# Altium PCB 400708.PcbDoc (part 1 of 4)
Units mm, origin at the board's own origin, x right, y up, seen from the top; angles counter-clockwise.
Board outline 117 x 63.5 mm, 4 copper layers (Top Layer, Mid-Layer 1, Mid-Layer 2, Bottom Layer), stack 1.556 mm thick; 226 components, 168 nets, 912 pads, 2002 vias.
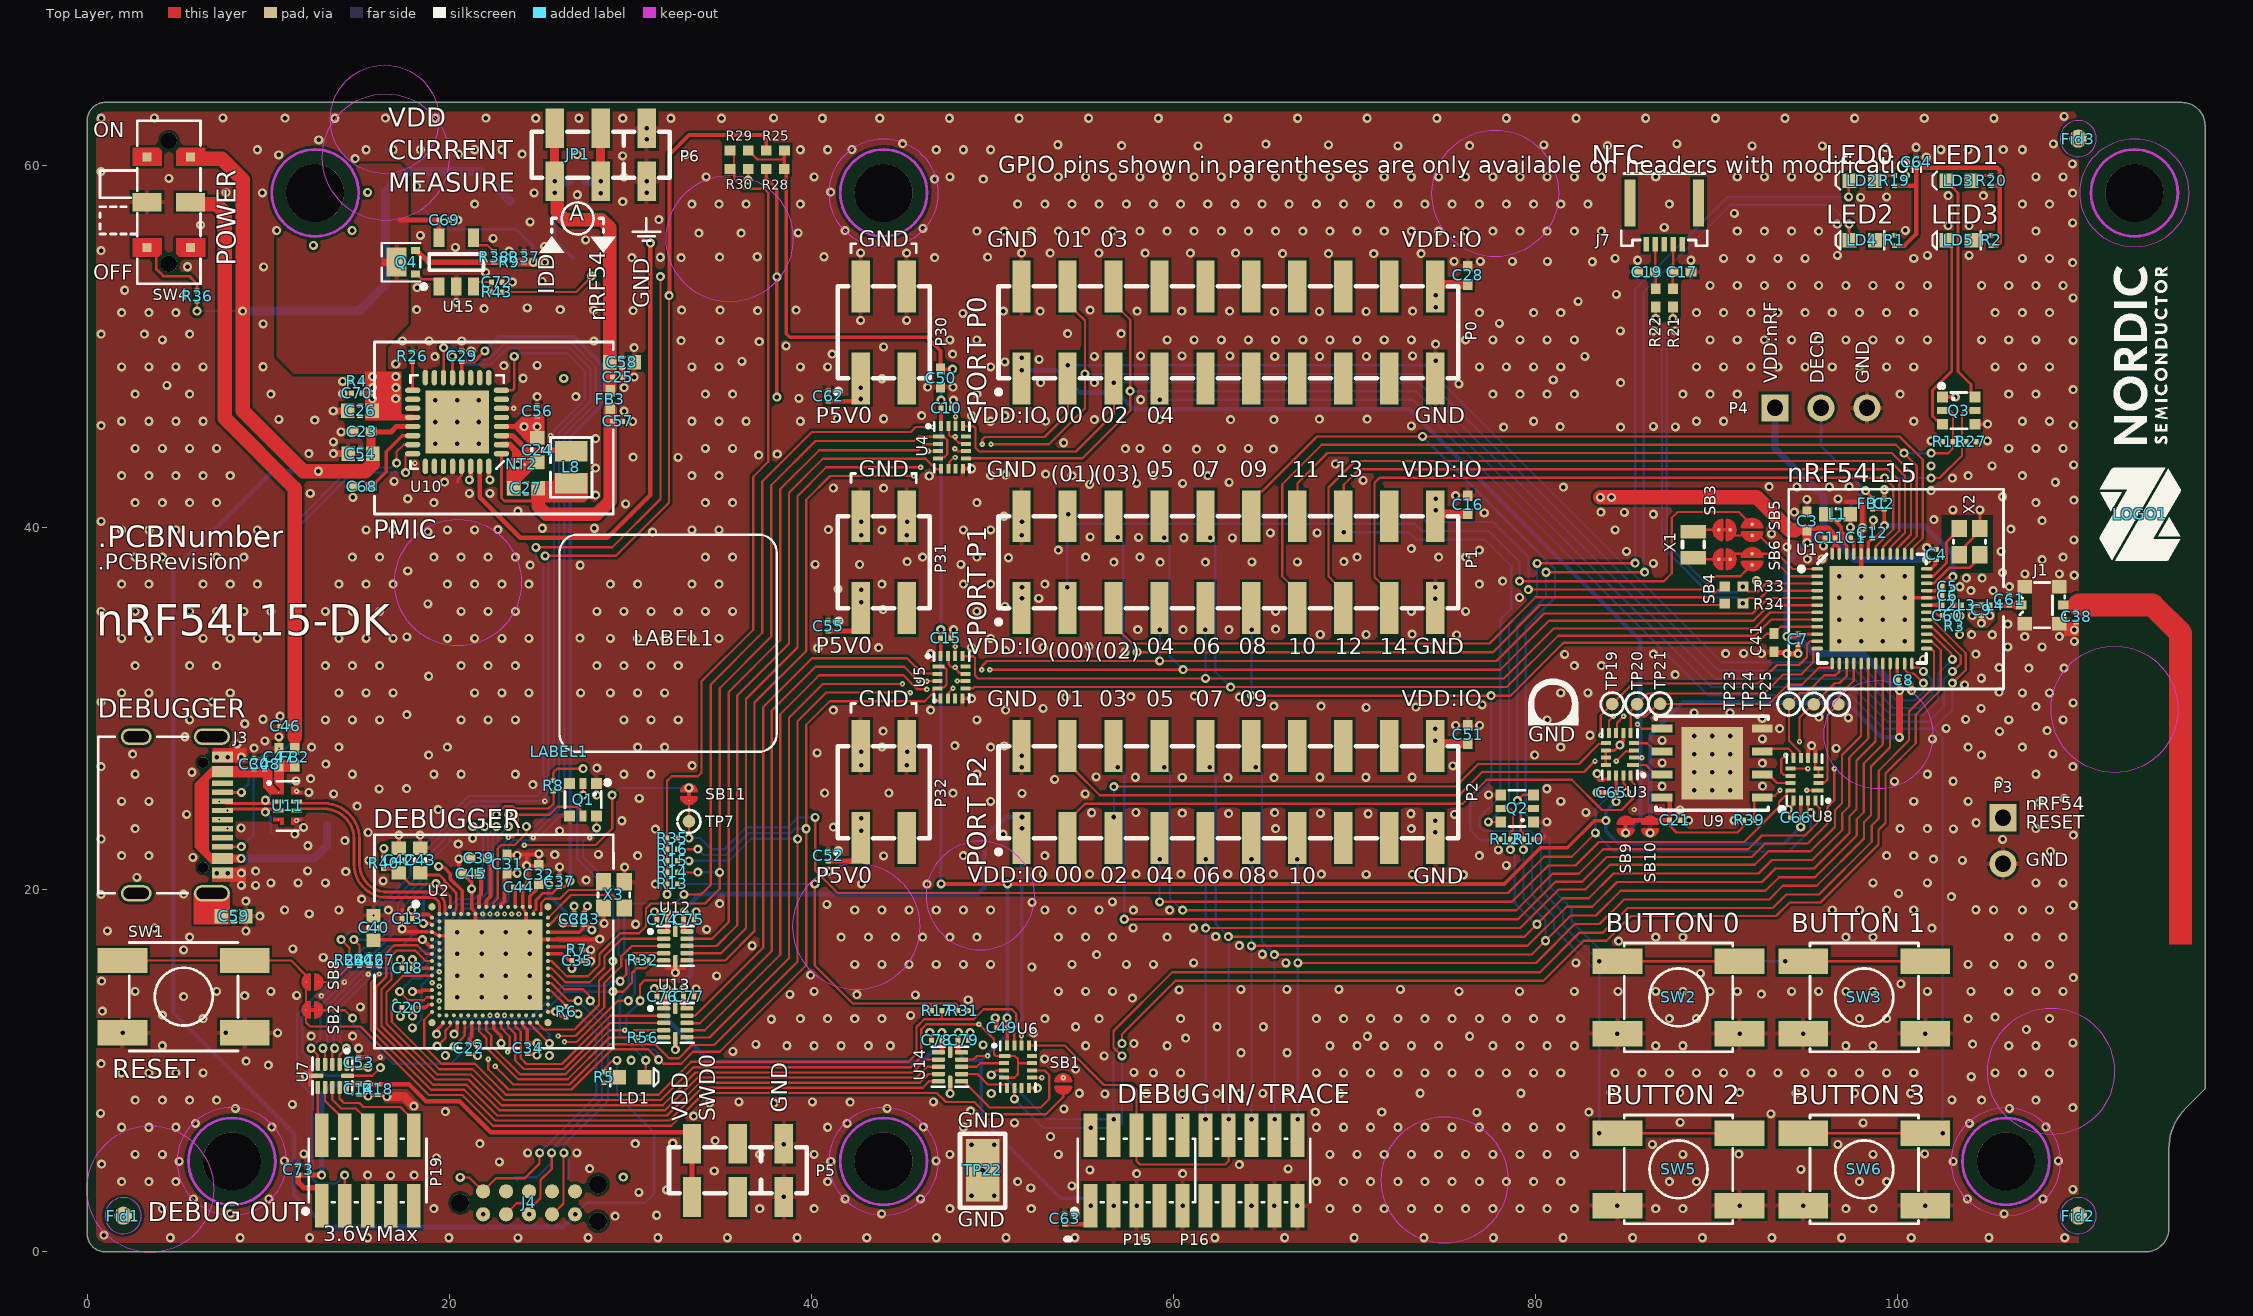
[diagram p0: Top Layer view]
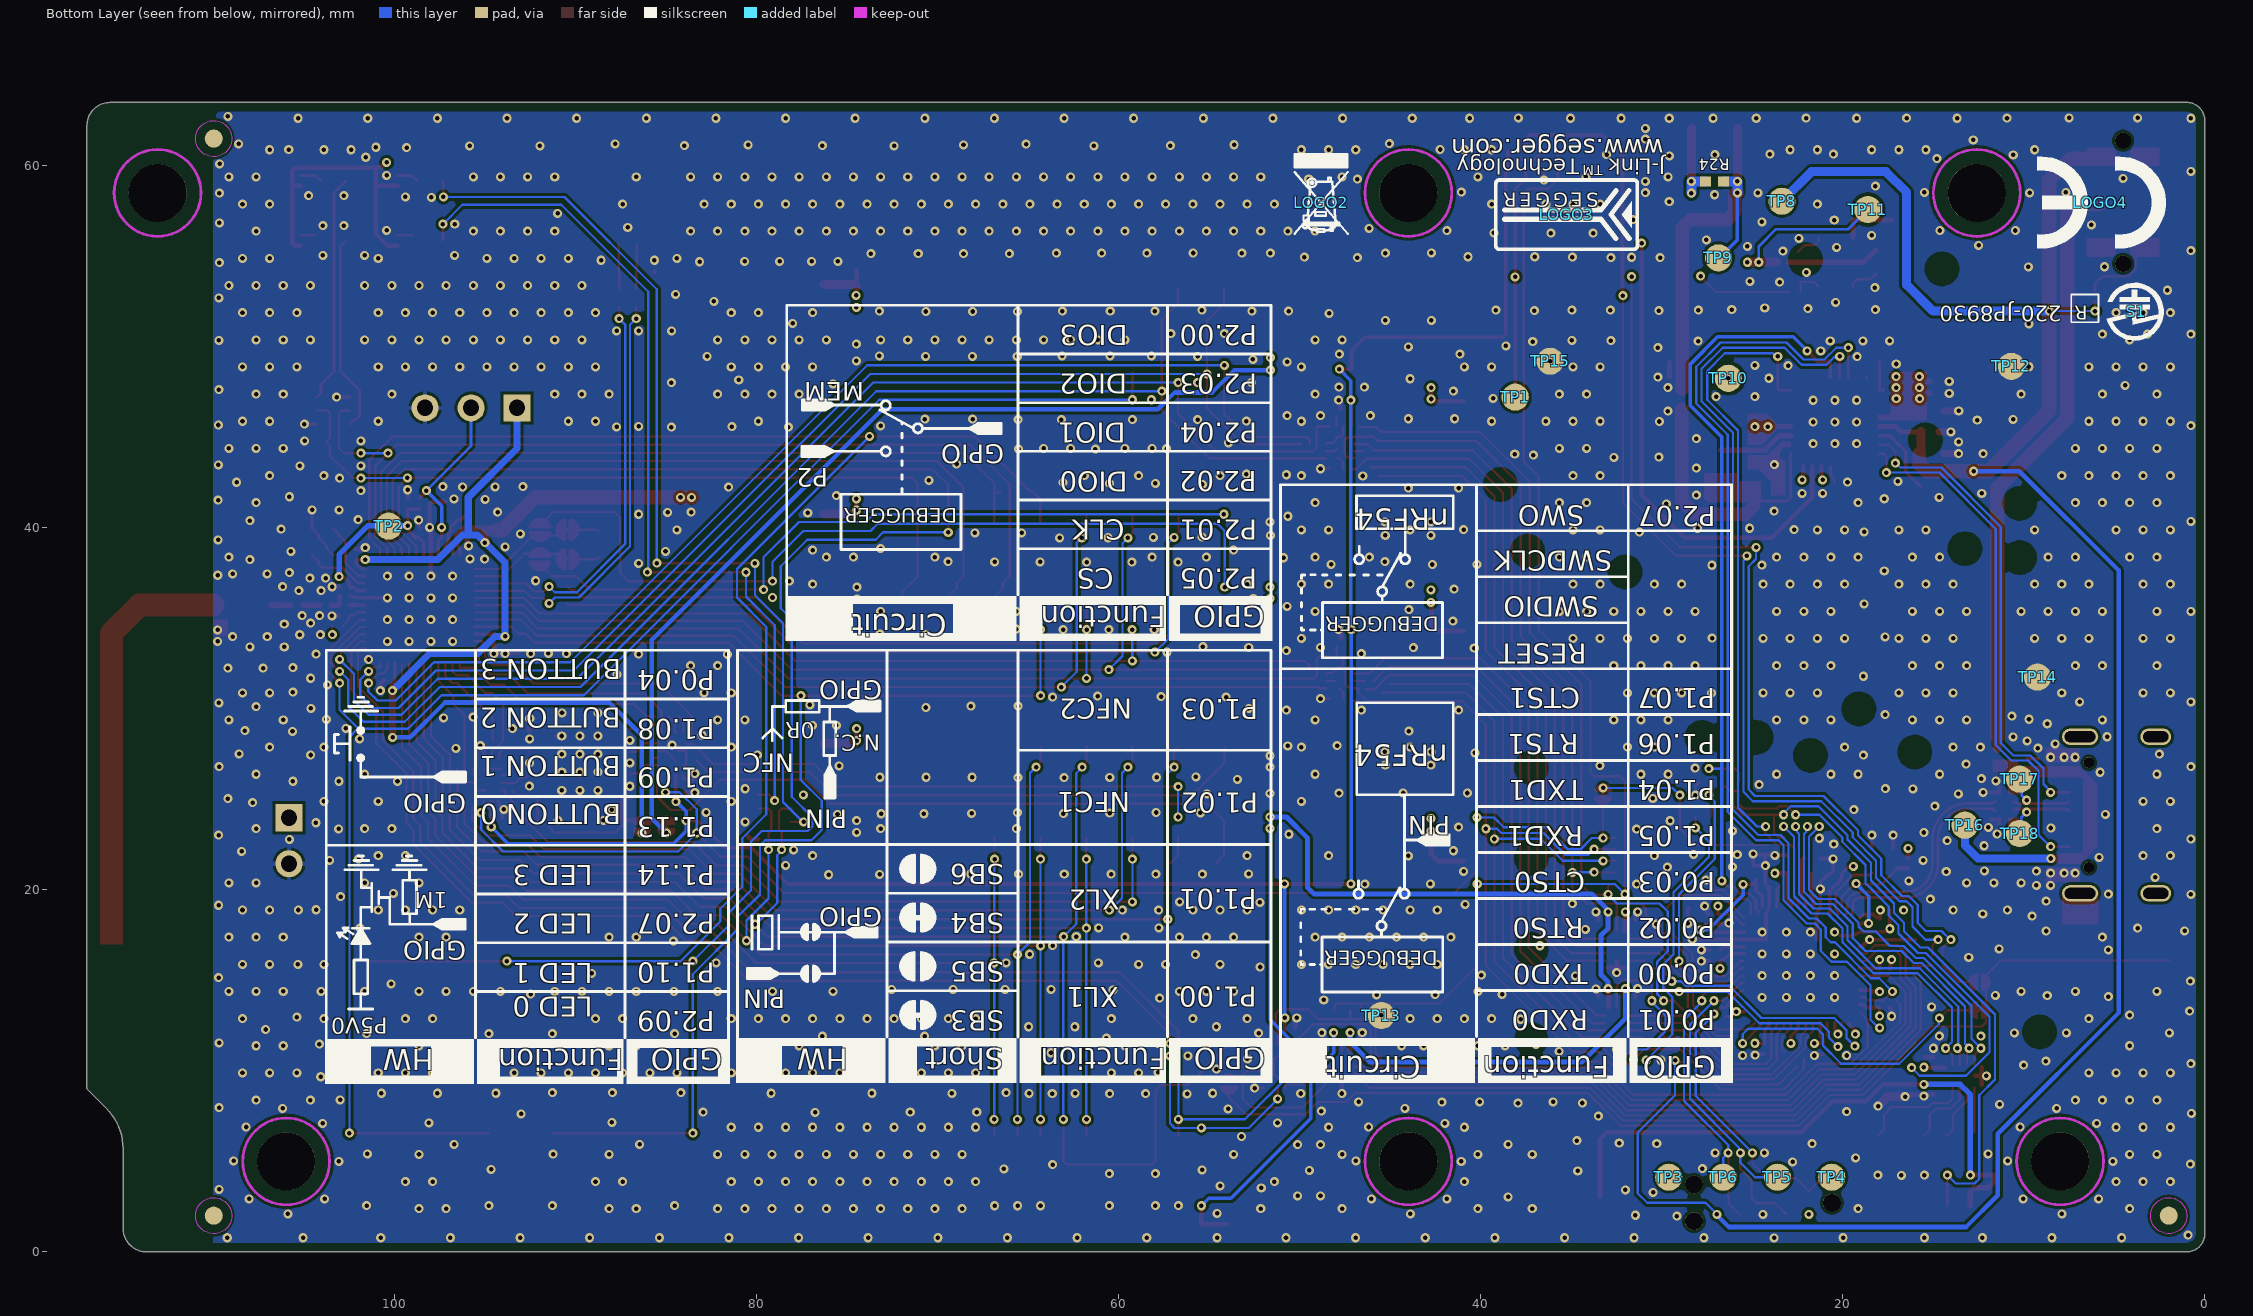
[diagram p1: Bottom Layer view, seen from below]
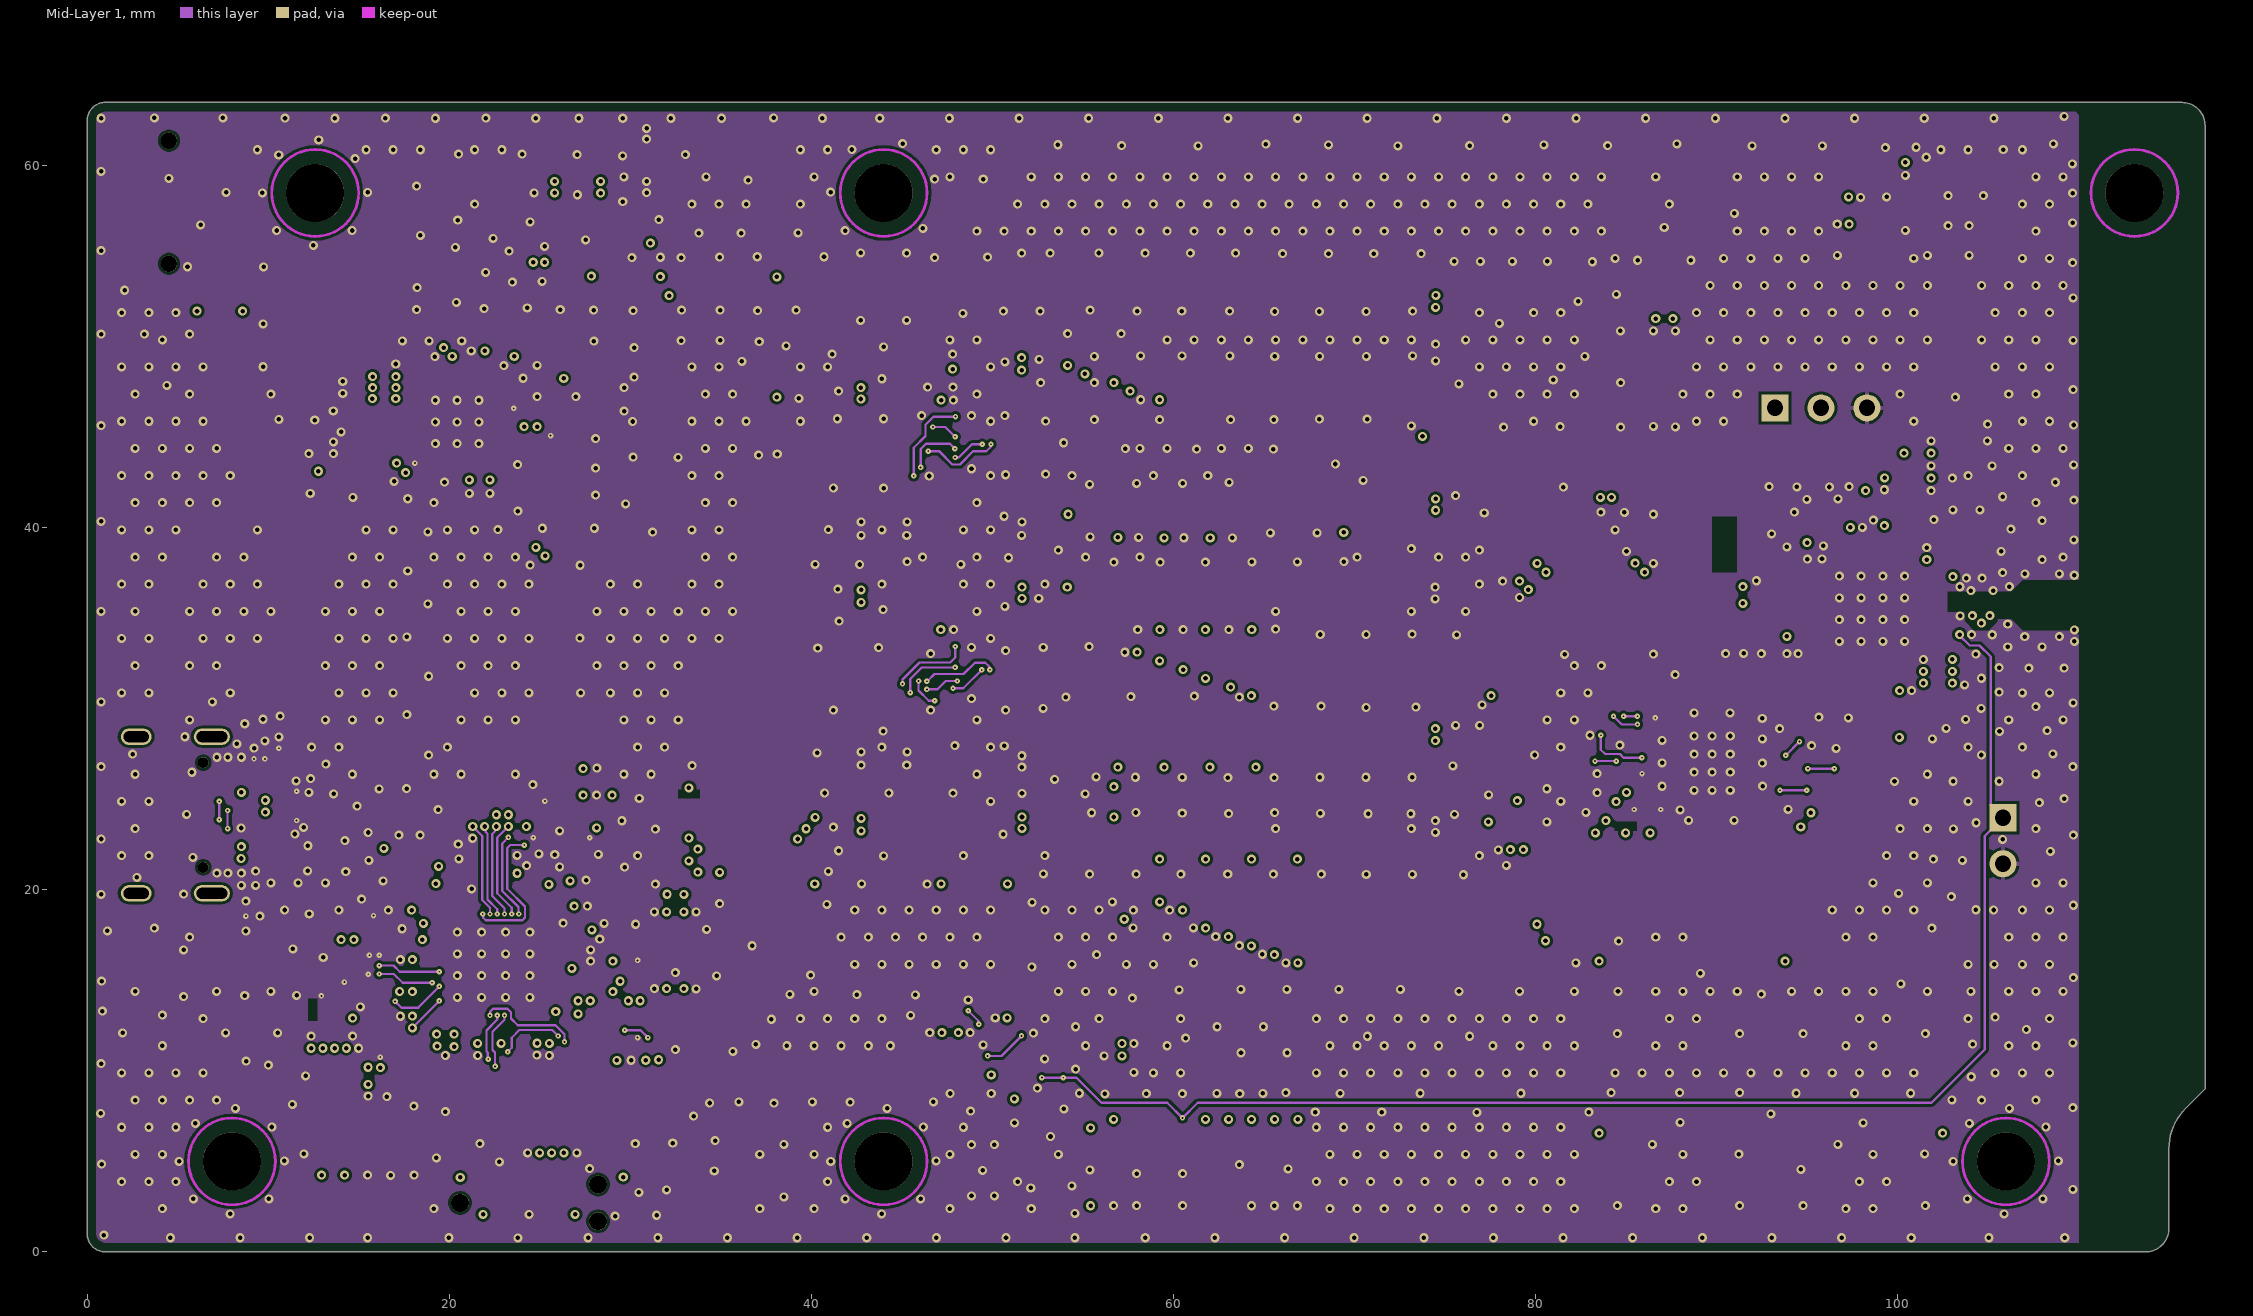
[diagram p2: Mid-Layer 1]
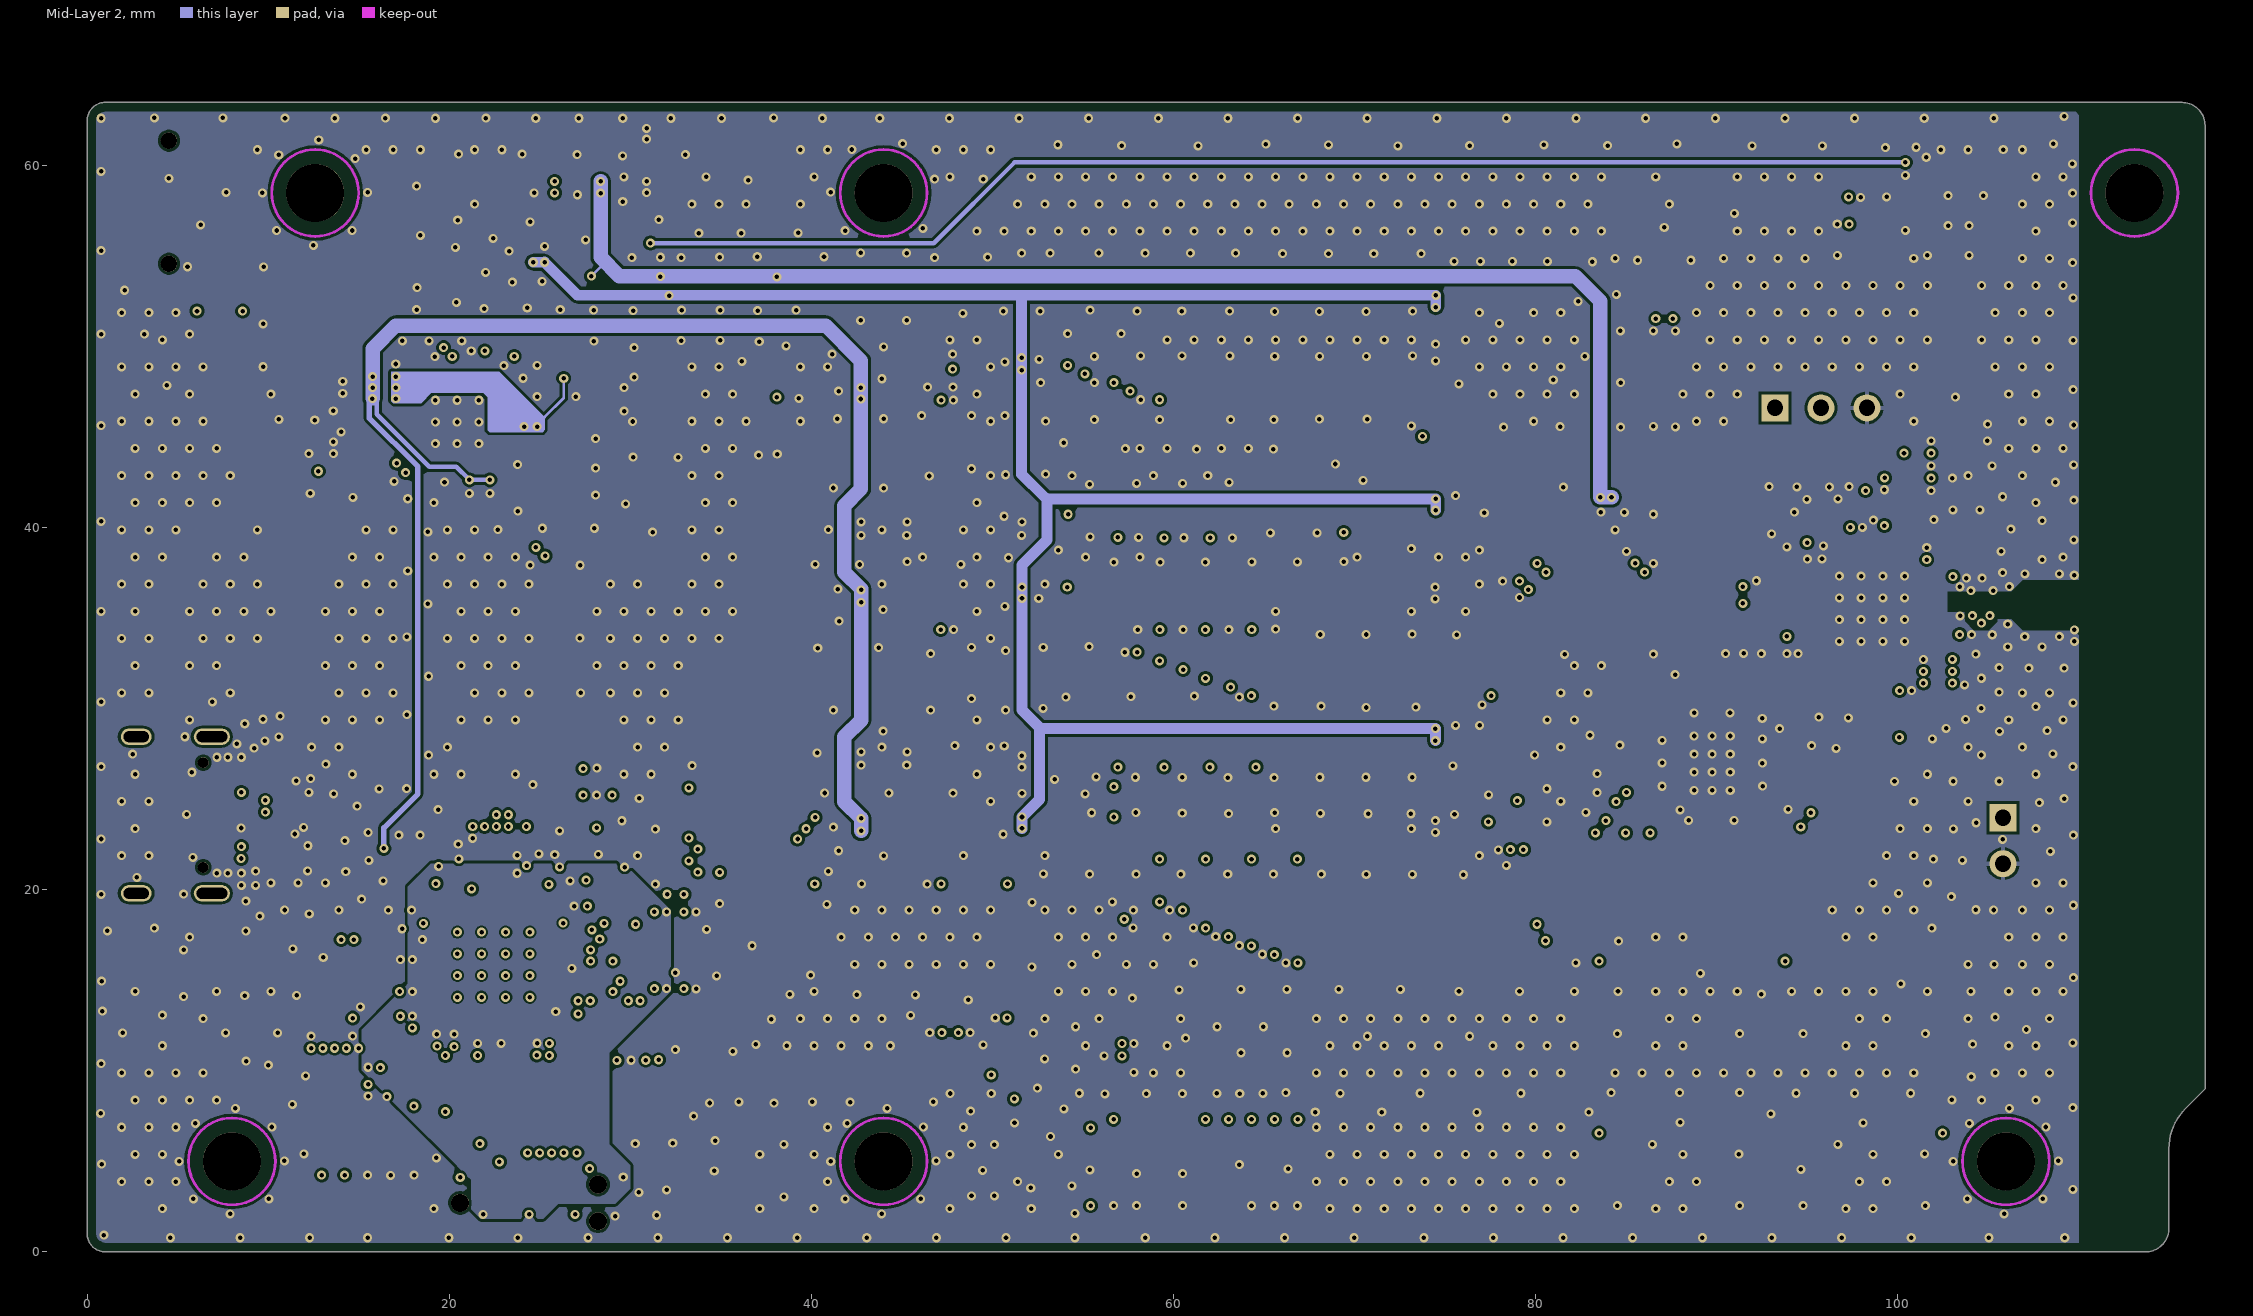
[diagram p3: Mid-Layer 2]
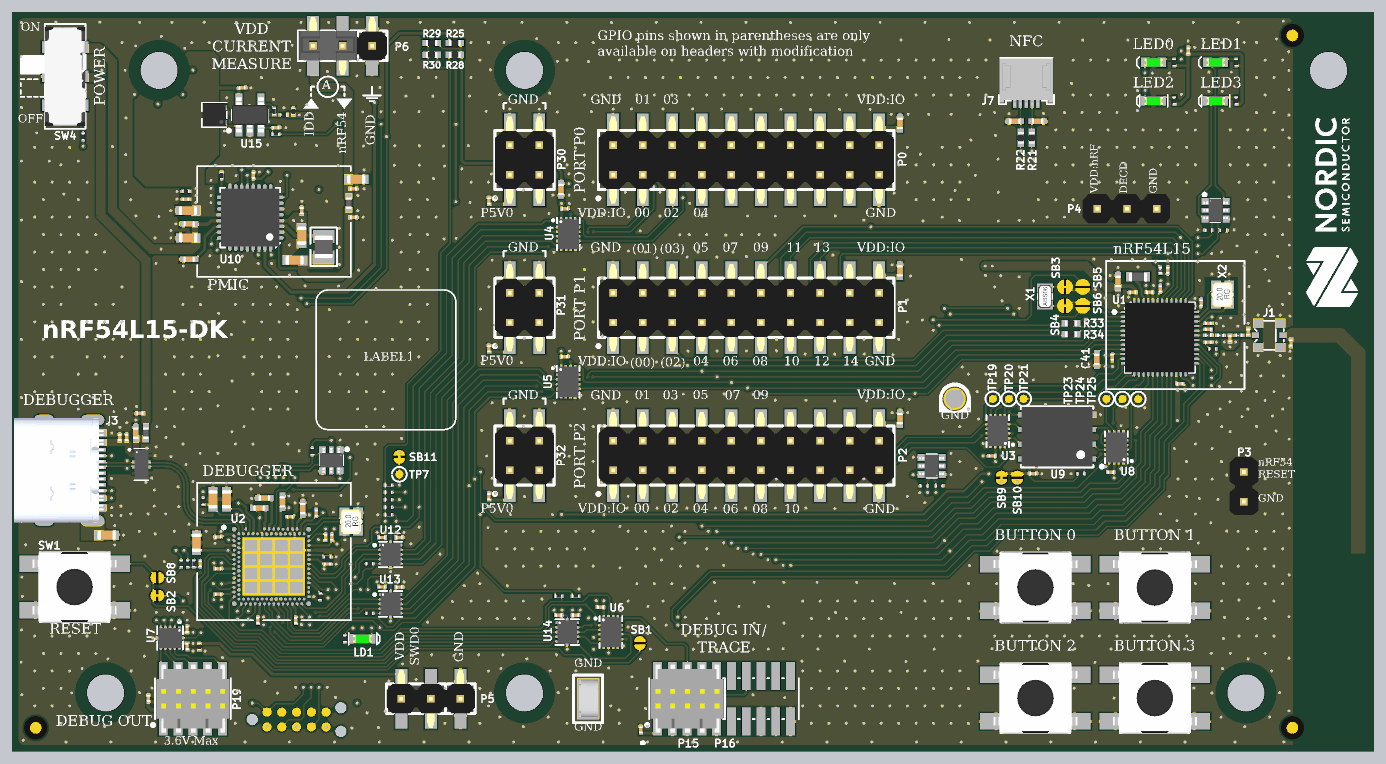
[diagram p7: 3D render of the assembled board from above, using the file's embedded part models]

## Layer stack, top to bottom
Top Solder: solder mask 0.0102, Solder Resist, Dk 3.5
Top Layer: signal copper 0.048
Dielectric 1: prepreg 0.1, PP-021, Dk 4.2
Mid-Layer 1: signal copper 0.03
Dielectric 2: core 1.2, Core-042, Dk 4.2
Mid-Layer 2: signal copper 0.03
Dielectric 3: prepreg 0.1, PP-021, Dk 4.2
Bottom Layer: signal copper 0.048
Bottom Solder: solder mask 0.0102, Solder Resist, Dk 3.5

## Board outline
1.016,0 cw(c1.016,1.016) 0,1.016 0,62.484 cw(c1.016,62.484) 1.016,63.5 115.734,63.5 cw(c115.734,62.23) 117.004,62.23 117.004,9 115.92,7.916 ccw(c118.132,5.705) 115.004,5.705 115.004,1.295 cw(c113.709,1.295) 113.709,0

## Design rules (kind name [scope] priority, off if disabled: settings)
AssemblyTestPointUsage [All] p1 off:
AssemblyTestpoint [All] p1 off: testpointundercomponent=TRUE minsize=1.016 maxsize=2.54 preferedsize=1.524 minholesize=0 maxholesize=1.016 preferedholesize=0.813 testpointgrid=0.025 usegrid=TRUE gridtolerance=0 allowsidetop=TRUE allowsidebottom=TRUE
BoardOutlineClearance [All] p1: gap=0.508 ignorepadtopadclearanceinfootprint=FALSE except(0: Arc-SplitContinuation Track-SplitContinuation SMDPad-SplitContinuation THPad-SplitContinuation Via-SplitContinuation Fill-SplitContinuation Poly-SplitContinuation Region-SplitContinuation Text-SplitContinuation)
Clearance ANT_Clearance [InNet('ANT') or InNet('RF') or InNet('NetC9_2') or InNet('NetC6_2')] p1: gap=0.16 ignorepadtopadclearanceinfootprint=FALSE
Clearance Polygon_Clearance [(InNamedPolygon('Mid_Layer1-GND')) or (InNamedPolygon('Bottom_Layer-GND')) or (InNamedPolygon('Mid_Layer2-GND')) or (InNamedPolygon('Top_Layer-GND'))] p2: gap=0.15 ignorepadtopadclearanceinfootprint=FALSE
Clearance Clearance_IMCU [WithinRoom('nRF5340')] p3: gap=0.1 ignorepadtopadclearanceinfootprint=FALSE
Clearance DiffPair_Clearance [InNetClass('IMCU_USB')] p4: gap=0.127 ignorepadtopadclearanceinfootprint=FALSE
Clearance [All] p5: gap=0.15 ignorepadtopadclearanceinfootprint=FALSE except(0.25: THPad-Region)
ComponentClearance [All] p1 off: gap=0.254 collisioncheckmode=3 verticalgap=0.254 showdistances=FALSE
DiffPairsRouting [InDifferentialPairClass('All Differential Pairs')] p1: maxlimit=0.15 minlimit=0.15 mostfreqgap=0.15 toplayer_minwidth=0.125 toplayer_maxwidth=0.153 toplayer_prefwidth=0.153 midlayer1_minwidth=0.125 midlayer1_maxwidth=0.153 midlayer1_prefwidth=0.125 midlayer4_minwidth=0.125 midlayer4_maxwidth=0.153 midlayer4_prefwidth=0.125 bottomlayer_minwidth=0.125 bottomlayer_maxwidth=0.153 bottomlayer_prefwidth=0.153 maxuncoupledlength=10
FabricationTestPointUsage TestPointUsage [All] p1 off: valid=2 allowmultiple=FALSE
FabricationTestpoint Testpoint [All] p1 off: side=2 testpointundercomponent=TRUE minsize=1.016 maxsize=2.54 preferedsize=1.524 minholesize=0 maxholesize=1.016 preferedholesize=0.813 testpointgrid=2.54 allowsidebottom=TRUE usegrid=TRUE gridtolerance=0
Height [All] p1 off: minheight=0 maxheight=25.4 prefheight=12.7
HoleSize [All] p1: absolutevalues=TRUE maxlimit=5 minlimit=0.1 maxpercent=80.000 minpercent=20.000
HoleToHoleClearance [IsThruVia] p1: gap=0.35 allowstackedmicrovias=FALSE
LayerPairs [All] p1 off: enforce=TRUE
MatchedLengths "Schematic Matched Net Lengths" [InNetClass('TRACE')] p1: tolerance=25.4 checknetsindiffpair=FALSE checkdiffpairvsdiffpair=TRUE checkxsignals=TRUE checkothers=TRUE usedelayunits=TRUE delaytolerance=500.000000
MatchedLengths MatchedLengths-Diffpairs [InDifferentialPairClass('All Differential Pairs')] p2: tolerance=1.27 checknetsindiffpair=TRUE checkdiffpairvsdiffpair=FALSE checkxsignals=FALSE checkothers=FALSE
MinimumAnnularRing [All] p1 off: minimumring=0.1
MinimumSolderMaskSliver [All] p1: minsoldermaskwidth=0.09
NetAntennae [All] p1 off: netantennaetolerance=0.3
PolygonConnect PolygonConnect_TP [HasFootprint('TP_SMD_D1.5mm') vs InNet('GND')] p1: connectstyle=Direct reliefconductorwidth=0.254 reliefentries=4 polygonreliefangle="90 Angle" airgapwidth=0.254
PolygonConnect PolygonConnect_SMT_Pads [HasFootprint('COAXIAL-SWF') or InComponent('C9') or InComponent('C61') or InComponent('TP22') or InComponent('U9') vs InNet('GND')] p2: connectstyle=Direct reliefconductorwidth=0.254 reliefentries=4 polygonreliefangle="90 Angle" airgapwidth=0.254
PolygonConnect [All] p3: thpad.connectstyle=Relief thpad.reliefconductorwidth=0.254 thpad.reliefentries=4 thpad.polygonreliefangle="90 Angle" thpad.airgapwidth=0.15 smdpad.connectstyle=Relief smdpad.reliefconductorwidth=0.254 smdpad.reliefentries=4 smdpad.polygonreliefangle="90 Angle" smdpad.airgapwidth=0.15 via.connectstyle=Direct via.reliefconductorwidth=0.254 via.reliefentries=4 via.polygonreliefangle="90 Angle" via.airgapwidth=0.254
RoomDefinition nRF5340 [False vs False] p1: confinementstyle=ConfineIn formatcopy=TRUE lockcomponents=FALSE outline 18.183,19.99 27.124,19.99 27.124,11.213 18.183,11.213
RoutingVias RoutingVias_Blind [IsBlindVia or IsMicroVia] p1: holewidth=0.711 width=1.27 viastyle="Through Hole" minholewidth=0.711 minwidth=1.27 maxholewidth=0.711 maxwidth=1.27 useviatemplates=TRUE viatemplateguid#1={B6F7EE11-84B8-42C4-BDC0-4B8B407402DD} viatemplatename#1=v30h10m0
RoutingVias RoutingVias_thru [IsThruVia] p2: holewidth=0.305 width=0.61 viastyle="Through Hole" minholewidth=0.305 minwidth=0.61 maxholewidth=0.711 maxwidth=1.27 useviatemplates=TRUE viatemplateguid#1={462064FF-42C7-473E-A651-561C1576AFDF} viatemplateguid#2={E64AB874-45CE-4CC8-95DD-841B5CDF8BA9} viatemplatename#1=v50h25m0mx0 viatemplatename#2=v50h25m0mx0(1)
ShortCircuit ShortCircuit_P15_P16 [InComponent('P15') vs InComponent('P16')] p1: allowed=TRUE
ShortCircuit ShortCircuit_PSS [InNet('PVSS1') or InNet('PVSS2') vs InNet('GND')] p2: allowed=TRUE
ShortCircuit [All] p3: allowed=FALSE
SignalStimulus [All] p1: kind=1 level=0 starttime=10.00n stoptime=250.0n periodtime=150.0n
SilkToSilkClearance [All] p1 off: silktosilkclearance=0.254
SilkToSolderMaskClearance SilkscreenOverComponentPads [IsPad] p1 off: minsilkscreentomaskgap=0.254 clearancetoexposedcopper=TRUE
SolderMaskExpansion SolderMaskExpansion_XFDFN40 [HasFootprint('XFDFN40P180X120X40-8M')] p1: expansion=0.02 istentingtop=FALSE
SolderMaskExpansion SolderMaskExpansion_footprints [HasFootprint('UDFN65P200X200X60_HS-6N') or HasFootprint('SON50P300X80-HS-11N') or HasFootprint('US8') or HasFootprint('SON50P300X80_HS-9N') or HasFootprint('BGA25C40P5X5_200X200X50') or HasFootprint('QFN40P180X140X55-10N') or HasFootprint('DX07S016JA1R1500') or HasFootprint('AQFN40P700X700X85_HS-99N') or HasFootprint('Nordic_QFN50P500X500X90-33N') or HasFootprint('QFN12P40_170X200X55L50X20')] p2: expansion=0.03 istentingtop=FALSE
SolderMaskExpansion SolderMaskExpansion_VIA [IsVia] p3: expansion=0.076 istentingtop=TRUE
SolderMaskExpansion [All] p4: expansion=0.05 istentingtop=FALSE
SupplyNets "Schematic Supply Nets" [InNet('VDD:IO')] p1: voltage=0.000
SupplyNets "Schematic Supply Nets_1" [InNet('VBUS')] p2: voltage=0.000
SupplyNets "Schematic Supply Nets_15" [InNet('VDD:SW')] p3: voltage=0.000
SupplyNets "Schematic Supply Nets_14" [InNet('VDD:DBGR')] p4: voltage=0.000
SupplyNets "Schematic Supply Nets_10" [InNet('VDD:SWD0')] p5: voltage=0.000
SupplyNets "Schematic Supply Nets_9" [InNet('VDD:nRF')] p6: voltage=0.000
SupplyNets "Schematic Supply Nets_7" [InNet('VDD:SW_PU')] p7: voltage=0.000
SupplyNets "Schematic Supply Nets_13" [InNet('VDD')] p8: voltage=0.000
SupplyNets "Schematic Supply Nets_12" [InNet('P5V0')] p9: voltage=0.000
SupplyNets "Schematic Supply Nets_11" [InNet('GND')] p10: voltage=0.000
SupplyNets "Schematic Supply Nets_3" [InNet('PVSS1')] p11: voltage=0.000
SupplyNets "Schematic Supply Nets_2" [InNet('VBUSOUT')] p12: voltage=0.000
Width Width_IMCU [OnTopLayer and HasFootprint('BGA144C35P12X12_450X420X100-A8-M3')] p1: maxlimit=2.5 minlimit=0.1 preferedwidth=0.15
Width [All] p2: maxlimit=2.5 minlimit=0.125 preferedwidth=0.15
15 further rules are at their usual default settings.

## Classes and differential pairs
component class Switches: C65 C66 R35 SB11 TP7 TP19 TP20 TP21 TP23 TP24 TP25 U3 U8
net class UART1: P1.04 P1.05 P1.06 P1.07
net class UART0: P0.00 P0.01 P0.02 P0.03
net class SWD_nRF54: nRF54_RESET P2.07 SWDCLK SWDIO
net class QSPI: P2.00_B P2.01_B P2.02_B P2.03_B P2.04_B P2.05_B
net class NFC: P1.02/NFC1 P1.03/NFC2
net class LEDS: P1.10 P1.14 P2.07 P2.09
net class GPIO_P2: P2.00 P2.01 P2.02 P2.03 P2.04 P2.05 P2.06 P2.07 P2.08 P2.09 P2.10
net class GPIO_P1: P1.00 P1.01 P1.02/NFC1 P1.03/NFC2 P1.04 P1.05 P1.06 P1.07 P1.08 P1.09 P1.10 P1.11 P1.12 P1.13 P1.14
net class GPIO_P0: P0.00 P0.01 P0.02 P0.03 P0.04
net class BUTTONS: P0.04 P1.08 P1.09 P1.13
differential pair class DBGR: DBGR DBGR'
net class DBGR_USB: DBGR'_N DBGR'_P DBGR_N DBGR_P
net class TRACE: P2.06 P2.07 P2.08 P2.09 P2.10
component class "Power supply": C23 C24 C25 C26 C27 C29 C56 C57 C58 C68 C69 C70 C72 FB3 JP1 L8 NT2 P6 Q4 R4 R24 R26 R38 R43 TP8 TP9 TP10 TP11 TP12 TP13 TP14 TP15 U10 U15
component class "Levelshifters and switches": C10 C14 C15 C49 C50 C53 C74 C75 C76 C77 C78 C79 R8 R13 R14 R15 R16 R17 R18 R25 R28 R29 R30 R31 U4 U5 U6 U7 U12 U13 U14
component class nRF54L15: C1 C2 C3 C4 C5 C6 C7 C8 C9 C11 C12 C38 C41 C60 C61 FB1 J1 L1 L2 L3 L4 P3 P4 R3 R33 R34 SB3 SB4 SB5 SB6 TP1 TP2 U1 X1 X2
component class Debugger: C13 C18 C20 C22 C31 C32 C33 C34 C35 C36 C37 C39 C40 C42 C43 C44 C45 C67 J4 LD1 Q1 R5 R6 R7 R32 R40 R41 R42 R56 TP3 TP4 TP5 TP6 U2 X3
component class Misc: C17 C19 C21 C64 LD2 LD3 LD4 LD5 Q2 Q3 R1 R2 R10 R11 R12 R19 R20 R21 R22 R23 R27 R39 SB8 SB9 SB10 SW1 SW2 SW3 SW5 SW6 U9
component class Connectors: C16 C28 C30 C46 C47 C48 C51 C52 C54 C55 C59 C62 C63 C73 FB2 J3 J7 P0 P1 P2 P5 P15 P16 P19 P30 P31 P32 R36 SW4 TP16 TP17 TP18 TP22 U11
component class pca10156_sheet1_connections: Fid1 Fid2 Fid3 LABEL1 LOGO1 LOGO2 LOGO3 LOGO4 S1 SB1 SB2
differential pair DBGR: +DBGR_P -DBGR_N
differential pair DBGR': +DBGR'_P -DBGR'_N

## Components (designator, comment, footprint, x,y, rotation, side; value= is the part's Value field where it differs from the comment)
C1 "2.2µF" CAPC0603X03L_C 97.72,39.439 r180 top
C2 "2.2µF" CAPC0603X03L_C 99.294,41.317 r270 top
C3 "10µF" CAPC1005X04L 95.017,40.367 r270 top
C4 "100nF" CAPC0603X03L_C 102.164,38.523 r90 top
C5 "2.2nF" CAPC0603X03L_C 102.773,36.75 r180 top
C6 "1.5pF" CAPC0603X03L_C 102.773,36.25 r0 top
C7 "100nF" CAPC0603X03L_C 94.518,33.849 r270 top
C8 "100nF" CAPC0603X03L_C 100.325,31.575 r0 top
C9 "2.0pF" CAPC0603X03L_C 104.635,35.445 r90 top
C10 "100nF" CAPC0603X03L_C 47.467,46.607 r0 top
C11 "100nF" CAPC0603X03L_C 96.285,39.439 r180 top
C12 "10nF" CAPC0603X03L_C 98.633,39.717 r90 top
C13 "100nF" CAPC0603X03L_C 17.689,18.401 r180 top
C14 "100nF" CAPC0603X03L_C 15.004,8.992 r270 top
C15 "100nF" CAPC0603X03L_C 47.433,33.903 r0 top
C16 "1.0µF" CAPC1005X04L 76.275,41.275 r270 top
C17 "300pF" CAPC1005X04L 88.104,54.123 r0 top
C18 "100nF" CAPC0603X03L_C 17.689,15.659 r180 top
C19 "300pF" CAPC1005X04L 86.152,54.123 r0 top
C20 "100nF" CAPC0603X03L_C 17.689,13.499 r180 top
C21 "100nF" CAPC0603X03L_C 87.707,23.842 r0 top
C22 "100nF" CAPC0603X03L_C 21.092,11.239 r270 top
C23 "2.2µF" CAPC1005X04L 15.184,45.313 r0 top
C24 "10µF" CAPC1608X06L 24.867,44.296 r90 top
C25 "100nF" CAPC0603X03L_C 29.305,48.321 r180 top
C26 "10µF" CAPC1608X06L 15.082,46.456 r0 top
C27 "10µF" CAPC1608X06L 24.249,42.186 r0 top
C28 "1.0µF" CAPC1005X04L 76.275,53.95 r270 top
C29 "100nF" CAPC0603X03L_C 20.7,49.475 r90 top
C30 "10nF" CAPC0603X03L_C 9.225,26.95 r90 top
C31 "1.0µF" CAPC1005X04L 23.2,21.424 r90 top
C32 "1.0µF" CAPC1005X04L 24.953,20.84 r270 top
C33 "2.2nF" CAPC0603X03L_C 27.459,18.376 r90 top
C34 "100nF" CAPC0603X03L_C 24.343,11.239 r270 top
C35 "100nF" CAPC0603X03L_C 27.068,16.078 r0 top
C36 "100nF" CAPC0603X03L_C 26.909,18.376 r270 top
C37 "100nF" CAPC0603X03L_C 26.096,20.459 r90 top
C38 "1.4pF" CAPC0603X03L_C 109.88,35.08 r90 top
C39 "1.0µF" CAPC1005X04L 21.651,21.754 r0 top
C40 "2.2µF" CAPC1608X06L 15.825,17.9 r90 top
C41 "100nF" CAPC1005X04L 93.186,33.655 r90 top
C42 "4.7µF" CAPC1608X06L 17.231,21.627 r90 top
C43 "4.7µF" CAPC1608X06L 18.4,21.627 r90 top
C44 "100nF" CAPC0603X03L_C 23.835,20.154 r0 top
C45 "1.0µF" CAPC1005X04L 21.194,20.891 r0 top
C46 "100nF" CAPC0603X03L_C 10.95,29.025 r0 top
C47 "1.0µF" CAPC1005X04L 10.6,27.325 r270 top
C48 "100nF" CAPC0603X03L_C 9.825,26.95 r270 top
C49 "100nF" CAPC0603X03L_C 50.54,12.369 r180 top
C50 "1.0µF" CAPC1005X04L 47.15,48.269 r90 top
C51 "1.0µF" CAPC1005X04L 76.275,28.576 r270 top
C52 "100nF" CAPC0603X03L_C 40.95,21.875 r270 top
C53 "100nF" CAPC0603X03L_C 15.004,10.459 r270 top
C54 "4.7µF" CAPC1608X06L 15.1,44.1 r180 top
C55 "100nF" CAPC0603X03L_C 40.95,34.575 r270 top
C56 "100nF" CAPC0603X03L_C 24.867,46.446 r270 top
C57 "100nF" CAPC0603X03L_C 29.305,45.874 r180 top
C58 "4.7µF" CAPC1608X06L 29.55,49.139 r0 top
C59 "10nF" CAPC1608X06L 8.1,18.552 r0 top
C60 "3.9pF" CAPC0603X03L_C 102.773,35.149 r0 top
C61 "0.3pF" CAPC0603X03L_C 106.2,36.015 r270 top
C62 "100nF" CAPC0603X03L_C 40.95,47.275 r270 top
C63 "100nF" CAPC0603X03L_C 54,1.825 r270 top
C64 "100nF" CAPC0603X03L_C 101.039,60.185 r270 top
C65 "100nF" CAPC0603X03L_C 84.193,25.365 r180 top
C66 "100nF" CAPC0603X03L_C 94.385,23.971 r180 top
C67 "10nF" CAPC0603X03L_C 16.145,16.1 r90 top
C68 "1.0µF" CAPC1005X04L 15.184,42.275 r0 top
C69 "100nF" CAPC0603X03L_C 19.735,57 r0 top
C70 "100nF" CAPC0603X03L_C 14.9,47.425 r0 top
C72 "100nF" CAPC0603X03L_C 22.635,53.575 r0 top
C73 "100nF" CAPC0603X03L_C 11.679,4.531 r270 top
C74 "100nF" CAPC0603X03L_C 31.766,18.354 r180 top
C75 "100nF" CAPC0603X03L_C 33.233,18.354 r0 top
C76 "100nF" CAPC0603X03L_C 31.766,14.104 r180 top
C77 "100nF" CAPC0603X03L_C 33.233,14.094 r0 top
C78 "100nF" CAPC0603X03L_C 46.939,11.679 r180 top
C79 "100nF" CAPC0603X03L_C 48.395,11.679 r0 top
FB1 "120R/0.2A" INDC0603X03L_C 98.633,41.317 r270 top
FB2 "120R/0.55A" INDC1005X04L 11.475,27.325 r90 top
FB3 "120R/0.55A" INDC1005X04L 28.905,47.096 r90 top
Fid1 "Fiducial mark" Fiducial 2,2 r0 top locked value=N.A.
Fid2 "Fiducial mark" Fiducial 110,2 r0 top locked value=N.A.
Fid3 "Fiducial mark" Fiducial 110,61.5 r0 top locked value=N.A.
J1 "MM8130-2600" COAXIAL-SWF 108.005,35.73 r90 top locked
J3 "USB-C 2.0" SD-80259-001 5.1,24.134 r270 top locked
J4 "TC2050-IDC" TC2050-IDC-NLFP 24.418,2.709 r0 top locked
J7 "FPC 0.5mm RA SMD" FPC_05P-0.5mm-RA-SMD 88.129,55.654 r180 top locked
JP1 "Shunt 2.54mm" Shunt_2.54mm_Vertical 27.113,60.625 r180 top
L1 "4.7µH" INDC1608X06L 96.728,40.758 r180 top
L2 "2.7nH" INDC0603X03L_C 102.773,35.73 r0 top
L3 "3.5nH" INDC0603X03L_C 103.83,35.73 r0 top
L4 "3.5nH" INDC0603X03L_C 105.406,35.73 r0 top
L8 "2.2µH" INDC2016X10N 26.749,43.336 r90 top locked
LABEL1 "12x12mm" LabelSilk_12x12 26.1,27.625 r0 top
LD1 "L0603G" LED_0603_G 30.103,9.652 r180 top
LD2 "L0603G" LED_0603_G 98.07,59.181 r0 top
LD3 "L0603G" LED_0603_G 103.404,59.181 r0 top
LD4 "L0603G" LED_0603_G 98.07,55.879 r0 top locked
LD5 "L0603G" LED_0603_G 103.404,55.879 r0 top locked
LOGO1 "Nordic Logo" NORDIC_LOGO_LYING 113.429,40.75 r90 top
LOGO2 "WEE Symbol" WEE_3x4.5mm 48.823,57.95 r0 bottom
LOGO3 "Segger Logo S" SEGGER_LOGO_S 35.267,57.301 r0 bottom
LOGO4 "CE Logo" CE_logo 5.771,57.97 r0 bottom
NT2 "Net tie" "2 PIN STARPOINT" 23.983,43.502 r180 top net-tie
P0 "Pin Hdr 2x10" HDR_2x10-SMD 63.054,50.8 r0 top
P1 "Pin Hdr 2x10" HDR_2x10-SMD 63.054,38.1 r0 top
P2 "Pin Hdr 2x10" HDR_2x10-SMD 63.054,25.4 r0 top
P3 "Pin List 1x2" LIST_1x2 105.845,22.713 r270 top
P4 "Pin List 1x3" LIST_1x3 95.785,46.625 r0 top locked
P5 "Pin List 1x3" LIST_1x3_SMD 38.5,4.5 r180 top locked
P6 "Pin List 1x3" LIST_1x3_SMD 30.912,60.606 r180 top locked
P15 "Pin Header 2x5, 1.27mm" HDR_2x5-SMD-1.27mm-K 57.978,4.5 r0 top locked
P16 "Pin Header 2x10, 1.27mm" HDR_2x10-SMD-1.27mm-NC 61.153,4.5 r0 top locked
P19 "Pin Header 2x5, 1.27mm" HDR_2x5-SMD-1.27mm-K 15.504,4.5 r0 top locked
P30 "Pin Header 2x2 SMD" HDR_2x2-SMD 44.004,50.8 r0 top
P31 "Pin Header 2x2 SMD" HDR_2x2-SMD 44.004,38.1 r0 top
P32 "Pin Header 2x2 SMD" HDR_2x2-SMD 44.004,25.4 r0 top
Q1 "NX138AKS" TSSOP6 27.401,24.983 r180 top
Q2 "NX138AKS" TSSOP6 79,24.5 r90 top
Q3 "NX138AKS" TSSOP6 103.4,46.475 r270 top
Q4 "PBSS4330PA" DFN105P200X65-3N_v2 17.35,54.675 r180 top
R1 "680R" RESC0603X03L_C 99.848,55.879 r270 top
R2 "680R" RESC0603X03L_C 105.182,55.879 r270 top
R3 "0R" RESC0603X03L_C 103.15,34.575 r0 top
R4 "10k" RESC0603X03L_C 14.9,48.091 r0 top
R5 "560R" RESC0603X03L_C 28.56,9.652 r90 top
R6 "100k" RESC0603X03L_C 26.46,13.271 r270 top
R7 "47R" RESC0603X03L_C 27.06,16.687 r0 top
R8 "100k" RESC0603X03L_C 25.76,25.74 r90 top
R9 "0R" RESC0603X03L_C 23.317,54.674 r0 top
R10 "1M0" RESC0603X03L_C 79.64,22.798 r0 top
R11 "1M0" RESC0603X03L_C 102.796,44.763 r180 top
R12 "1M0" RESC0603X03L_C 78.336,22.792 r180 top
R13 "100k" RESC0603X03L_C 32.325,20.325 r0 top
R14 "100k" RESC0603X03L_C 32.325,20.964 r0 top
R15 "100k" RESC0603X03L_C 32.325,21.605 r0 top
R16 "100k" RESC0603X03L_C 32.325,22.237 r0 top
R17 "100k" RESC0603X03L_C 46.939,13.325 r180 top
R18 "1M0" RESC0603X03L_C 16.064,8.977 r90 top
R19 "680R" RESC0603X03L_C 99.848,59.181 r270 top
R20 "680R" RESC0603X03L_C 105.182,59.181 r270 top
R21 "0R" RESC1005X04L 87.604,52.704 r90 top
R22 "0R" RESC1005X04L 86.661,52.704 r90 top
R23 "100k" RESC0603X03L_C 14.5,16.1 r90 top
R24 "TBD" RESC1005X04L 27.099,59.141 r180 bottom
R25 "0R" RESC1005X04L 38.025,60.85 r0 top
R26 "47k" RESC0603X03L_C 17.973,49.468 r90 top
R27 "1M0" RESC0603X03L_C 104.075,44.763 r0 top
R28 "0R" RESC1005X04L 38.019,59.83 r0 top
R29 "0R" RESC1005X04L 36.025,60.85 r0 top
R30 "0R" RESC1005X04L 36.025,59.83 r0 top
R31 "100k" RESC0603X03L_C 48.395,13.325 r0 top
R32 "100k" RESC0603X03L_C 30.7,16.1 r180 top
R33 "0R" RESC1005X04L 90.974,36.755 r180 top
R34 "0R" RESC1005X04L 90.974,35.83 r180 top
R35 "100k" RESC0603X03L_C 32.325,22.864 r180 top
R36 "1k" RESC0603X03L_C 6.075,52.8 r270 top
R37 "10k" RESC0603X03L_C 24.142,54.96 r270 top
R38 "0R" RESC0603X03L_C 22.485,54.96 r270 top
R39 "100k" RESC0603X03L_C 91.822,23.835 r180 top
R40 "2R2" RESC0603X03L_C 16.394,21.469 r90 top
R41 "10k" RESC0603X03L_C 15.053,16.099 r90 top
R42 "10k" RESC0603X03L_C 15.6,16.099 r270 top
R43 "33k" RESC0603X03L_C 22.635,53.025 r180 top
R56 "100k" RESC0603X03L_C 30.7,11.84 r180 top
S1 "Giteki Symbol" Giteki 3.788,51.95 r0 bottom
SB1 "Solderbridge" Solderbridge 53.925,9.275 r270 top
SB2 "Solderbridge" Solderbridge_Shorted 12.45,13.364 r0 top net-tie
SB3 "Solderbridge" Solderbridge_SHORTED_0.4 90.458,39.887 r180 top net-tie
SB4 "Solderbridge" Solderbridge_SHORTED_0.4 90.458,38.262 r180 top net-tie
SB5 "Solderbridge" Solderbridge_0.4#1 91.982,39.887 r90 top
SB6 "Solderbridge" Solderbridge_0.4#2 91.982,38.262 r270 top
SB8 "Solderbridge" Solderbridge 12.45,14.91 r0 top
SB9 "Solderbridge" Solderbridge_Shorted 84.997,23.492 r90 top net-tie
SB10 "Solderbridge" Solderbridge 86.347,23.492 r90 top
SB11 "Solderbridge" Solderbridge_Shorted 33.25,25.283 r270 top net-tie
SW1 "PB SW" Switch-PB-6.2x6.3mm-SMD 5.338,14.097 r180 top
SW2 "PB SW" Switch-PB-6.2x6.3mm-SMD 87.918,14.058 r180 top locked
SW3 "PB SW" Switch-PB-6.2x6.3mm-SMD 98.179,14.058 r180 top locked
SW4 "Switch" JS102011JAQN 4.521,57.988 r270 top locked
SW5 "PB SW" Switch-PB-6.2x6.3mm-SMD 87.918,4.558 r180 top locked
SW6 "PB SW" Switch-PB-6.2x6.3mm-SMD 98.179,4.558 r180 top locked
TP1 "Ø1.5mm,SMD" TP_SMD_D1.5mm#1 38.104,47.219 r90 bottom locked
TP2 "Ø1.5mm,SMD" TP_SMD_D1.5mm#1 100.339,40.093 r180 bottom locked
TP3 "Ø1.5mm,SMD" TP_SMD_D1.5mm#2 29.62,4.115 r180 bottom locked
TP4 "Ø1.5mm,SMD" TP_SMD_D1.5mm#2 20.616,4.115 r180 bottom locked
TP5 "Ø1.5mm,SMD" TP_SMD_D1.5mm#2 23.616,4.115 r180 bottom locked
TP6 "Ø1.5mm,SMD" TP_SMD_D1.5mm#2 26.616,4.115 r180 bottom locked
TP7 "Ø0.7mm,SMD" TP_SMD_D0.7mm 33.25,23.783 r0 top
TP8 "Ø1.5mm,SMD" TP_SMD_D1.5mm#1 23.372,58.039 r270 bottom locked
TP9 "Ø1.5mm,SMD" TP_SMD_D1.5mm#1 26.877,54.915 r270 bottom locked
TP10 "Ø1.5mm,SMD" TP_SMD_D1.5mm#1 26.334,48.26 r180 bottom locked
TP11 "Ø1.5mm,SMD" TP_SMD_D1.5mm#1 18.622,57.582 r90 bottom locked
TP12 "Ø1.5mm,SMD" TP_SMD_D1.5mm#1 10.693,48.92 r90 bottom locked
TP13 "Ø1.5mm,SMD" TP_SMD_D1.5mm#1 45.496,13.056 r90 bottom locked
TP14 "Ø1.5mm,SMD" TP_SMD_D1.5mm#1 9.25,31.75 r90 bottom locked
TP15 "Ø1.5mm,SMD" TP_SMD_D1.5mm#1 36.174,49.2 r90 bottom locked
TP16 "Ø1.5mm,SMD" TP_SMD_D1.5mm#1 13.263,23.571 r180 bottom locked
TP17 "Ø1.5mm,SMD" TP_SMD_D1.5mm#1 10.24,26.115 r180 bottom locked
TP18 "Ø1.5mm,SMD" TP_SMD_D1.5mm#1 10.24,23.113 r180 bottom locked
TP19 "Ø0.7mm,SMD" TP_SMD_D0.7mm 84.253,30.265 r90 top
TP20 "Ø0.7mm,SMD" TP_SMD_D0.7mm 85.628,30.265 r90 top
TP21 "Ø0.7mm,SMD" TP_SMD_D0.7mm 86.9,30.275 r90 top
TP22 "TP" S1751 49.475,4.5 r270 top locked
TP23 "Ø0.7mm,SMD" TP_SMD_D0.7mm 94.016,30.265 r90 top
TP24 "Ø0.7mm,SMD" TP_SMD_D0.7mm 95.391,30.25 r90 top
TP25 "Ø0.7mm,SMD" TP_SMD_D0.7mm 96.75,30.25 r90 top
U1 "nRF54L15-QFAA" QFN40P600X600X90-48N 98.605,35.53 r0 top locked
U2 "nRF5340-QKAA" AQFN40P700X700X85_HS-99N 22.26,15.864 r0 top locked
U3 "TMUX1574" XQFN40P180X260X50-16N#1 84.675,27.5 r180 top
U4 "TMUX1511" XQFN40P180X260X50-16N#2 47.778,44.437 r0 top
U5 "TMUX1511" XQFN40P180X260X50-16N#2 47.76,31.736 r0 top
U6 "TMUX1511" XQFN40P180X260X50-16N#2 51.425,10.225 r0 top
U7 "TXB0104" QFN12P40_170X200X55L50X20 13.55,9.725 r270 top
U8 "TMUX1574" XQFN40P180X260X50-16N#1 94.875,26.1 r180 top
U9 "MX25R6435F" SON127P600X80_HS-9N 89.775,27 r180 top locked
U10 "nPM1300-QEAAC0" Nordic_QFN50P500X500X90-33N 20.442,45.846 r180 top locked
U11 "ECMF02-4CMX8" UFDFN50P120X250X55-8N 11.079,24.633 r0 top
U12 "TXB0104" QFN12P40_170X200X55L50X20 32.5,16.9 r0 top
U13 "TXB0104" QFN12P40_170X200X55L50X20 32.5,12.65 r0 top
U14 "TXB0104" QFN12P40_170X200X55L50X20 47.675,10.225 r0 top
U15 "TLV271" SOT95P280X145-5N 20.4,54.675 r90 top
X1 "32.768kHz" XTAL_2012 88.739,39.068 r90 top
X2 "32MHz" BT-XTAL_2016 103.993,39.234 r90 top
X3 "32MHz" BT-XTAL_2016 29.106,19.719 r90 top locked

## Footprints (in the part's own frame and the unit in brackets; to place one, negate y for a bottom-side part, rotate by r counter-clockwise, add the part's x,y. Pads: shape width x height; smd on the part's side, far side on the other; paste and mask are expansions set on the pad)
"2 PIN STARPOINT" [mil]
  round 6 smd paste-196.85 mask-196.85: 1(8,0) 2(-8,0)
  Top Layer region: -8,-3 8,-3 8,3 -8,3
AQFN40P700X700X85_HS-99N [mm] "AQFN, 98-Leads, Body 7.00x7.00mm, Pitch 0.40mm, Thermal Pad 5.4x5.0mm, IPC Medium Density"
  rect 5.4x5 smd paste-5: 104(0.2,0)
  round 0.4 smd paste+0.012: A1(-3.2,3.2) A31(3.2,3.2) AL1(-3.2,-3.2) AL31(3.2,-3.2)
  round 0.225 smd paste+0.012: A5(-2.2,3.2) A13(-0.6,3.2) A15(-0.2,3.2) A17(0.2,3.2) A19(0.6,3.2) A21(1,3.2) A23(1.4,3.2) A25(1.8,3.2) A27(2.2,3.2) AA1(-3.2,-1) AA31(3.2,-1) AB2(-2.8,-1.2) AC1(-3.2,-1.4) AC31(3.2,-1.4) AD2(-2.8,-1.6) AE1(-3.2,-1.8) AE31(3.2,-1.8) AF2(-2.8,-2) AG1(-3.2,-2.2) AG31(3.2,-2.2) AH2(-2.8,-2.4) AJ1(-3.2,-2.6) AJ31(3.2,-2.6) AK2(-2.8,-2.8) AK4(-2.4,-2.8) AK6(-2,-2.8) AK8(-1.6,-2.8) AK10(-1.2,-2.8) AK12(-0.8,-2.8) AK14(-0.4,-2.8) AK16(0,-2.8) AK18(0.4,-2.8) AK20(0.8,-2.8) AK22(1.2,-2.8) AK24(1.6,-2.8) AK26(2,-2.8) AK28(2.4,-2.8) AK30(2.8,-2.8) AL3(-2.6,-3.2) AL5(-2.2,-3.2) AL7(-1.8,-3.2) AL9(-1.4,-3.2) AL11(-1,-3.2) AL13(-0.6,-3.2) AL15(-0.2,-3.2) AL17(0.2,-3.2) AL19(0.6,-3.2) AL21(1,-3.2) AL23(1.4,-3.2) AL25(1.8,-3.2) AL27(2.2,-3.2) AL29(2.6,-3.2) B2(-2.8,2.8) B4(-2.4,2.8) B6(-2,2.8) B8(-1.6,2.8) B10(-1.2,2.8) B12(-0.8,2.8) B14(-0.4,2.8) B16(0,2.8) B18(0.4,2.8) B20(0.8,2.8) B22(1.2,2.8) B24(1.6,2.8) B26(2,2.8) B28(2.4,2.8) B30(2.8,2.8) C1(-3.2,2.6) C31(3.2,2.6) D2(-2.8,2.4) E1(-3.2,2.2) E31(3.2,2.2) F2(-2.8,2) G1(-3.2,1.8) G31(3.2,1.8) H2(-2.8,1.6) J1(-3.2,1.4) J31(3.2,1.4) K2(-2.8,1.2) L1(-3.2,1) L31(3.2,1) M2(-2.8,0.8) N1(-3.2,0.6) N31(3.2,0.6) P2(-2.8,0.4) R1(-3.2,0.2) R31(3.2,0.2) T2(-2.8,0) U1(-3.2,-0.2) U31(3.2,-0.2) V2(-2.8,-0.4) W1(-3.2,-0.6) W31(3.2,-0.6) Y2(-2.8,-0.8)
  rrect15% 1.1x1 on Top Paste: ""(-1.75,-1.8) ""(-1.75,-0.6) ""(-1.75,0.6) ""(-1.75,1.8) ""(-0.45,-1.8) ""(-0.45,-0.6) ""(-0.45,0.6) ""(-0.45,1.8) ""(0.85,-1.8) ""(0.85,-0.6) ""(0.85,0.6) ""(0.85,1.8) ""(2.15,-1.8) ""(2.15,-0.6) ""(2.15,0.6) ""(2.15,1.8)
  silkscreen extent -4.22,3.23 -3.97,3.47, body extent -3.5,-3.5 3.5,3.5, height 0.85
BT-XTAL_2016 [mm] "Crystal 2.0 x 1.6 mm"
  rect 0.95x0.85 smd: 1(-0.725,-0.575) 2(0.725,-0.575) 3(0.725,0.575) 4(-0.725,0.575)
  silkscreen extent -0.1,-0.88 0.1,0.88, body extent -1.05,-0.85 1.05,0.85, height 0.56
CAPC0603X03L_C [mm] "Chip Capacitor, 2-Leads, Body 0.6x0.3mm, IPC High Density"
  rect 0.27x0.3 smd mask+0.05: 1(-0.285,0) 2(0.285,0)
  body extent -0.3,-0.15 0.3,0.15, height 0.3
CAPC1005X04L [mm] "Chip Capacitor, 2-Leads, Body 1.0x0.5mm, IPC High Density"
  rect 0.6x0.5 smd: 1(-0.5,0) 2(0.5,0)
  body extent -0.5,-0.25 0.5,0.25, height 0.5
CAPC1608X06L [mm] "Chip Capacitor, 2-Leads, Body 1.6x0.8mm, IPC High Density"
  rect 0.75x0.8 smd: 1(-0.675,0) 2(0.675,0)
  silkscreen extent -0.1,-0.3 0.1,0.3, body extent -0.8,-0.4 0.8,0.4, height 0.8
CE_logo [mm]
  silkscreen extent -3.6,-2.53 3.48,2.53
COAXIAL-SWF [mm]
  rect 0.5x0.58 smd: 1(0,1.16) 3(0,-1.16)
  rect 0.75x0.8 smd: 2(-1.025,-0.95) 2(-1.025,0.95) 2(1.025,-0.95) 2(1.025,0.95)
  Top Layer pour cut-out: 0.65,-0.55 -0.65,-0.55 -0.65,-1.35 0.65,-1.35
  Top Layer pour cut-out: -0.65,0.55 0.65,0.55 0.65,1.35 -0.65,1.35
  silkscreen extent -1.25,-1.25 1.25,1.23, body extent -1.26,-1.3 1.26,1.3, height 1.55
DFN105P200X65-3N_v2 [mm] "DFN, 3-Leads, Body 2.00x2.00mm, Pitch 1.05mm, IPC Medium Density"
  rect 0.5x0.4 smd: 1(-0.8,0.65) 2(-0.8,-0.65)
  rect 1.1x1.6 smd: 3(0.25,0)
  Top Layer region: 0.65,-0.2 1.05,-0.2 1.05,0.2 0.65,0.2
  silkscreen extent -1.2,-1.06 1.06,1.36, body extent -1,-1 1,1, height 0.65
Fiducial [mm] "Fiducial Mark"
  round 1 smd paste-2539.97 mask+0.5: 0(0,0)
  round 1 smd far side paste-2539.97 mask+0.5: 0(0,0)
  Top Layer keep-out circle w0.01: c0,0 r1
  Bottom Layer keep-out circle w0.01: c0,0 r1
FPC_05P-0.5mm-RA-SMD [mm] "FPC, 5-Leads, Pitch 0,5mm"
  rect 0.6x2.6 smd: 0(-0.9,-2.3) 0(2.9,-2.3)
  rect 0.3x0.8 smd mask+0.05: 1(0,0) 2(0.5,0) 3(1,0) 4(1.5,0) 5(2,0)
  silkscreen extent -1.38,-3.93 3.38,0.08, body extent -1.3,-3.85 3.3,0.2, height 1.2
Giteki [mm] "Japan certification mark"
  silkscreen extent -1.5,-1.59 3.6,1.6
HDR_2x2-SMD [mil] "Board-Board Conn, Header, 4-way, 2-row"
  rect 40x113 smd: 1(-50,-100) 2(-50,100) 3(50,-100) 4(50,100)
  silkscreen extent -105,-135 100,100, body extent -100,-148 100,148, height 382
HDR_2x5-SMD-1.27mm-K [mm] "SMT MICRO HEADER, (1,27) .050\" Keying Shroud"
  rect 0.76x2.4 smd: 1(-2.54,-1.95) 2(-2.54,1.95) 3(-1.27,-1.95) 4(-1.27,1.95) 5(0,-1.95) 6(0,1.95) 7(1.27,-1.95) 8(1.27,1.95) 9(2.54,-1.95) 10(2.54,1.95)
  silkscreen extent -3.56,-2.38 3.25,1.75, body extent -3.14,-2.92 3.14,2.92, height 6.11
HDR_2x10-SMD [mil] "Board-Board Conn, Header, 20-way, 2-row"
  rect 40x113 smd: 1(-450,-100) 2(-450,100) 3(-350,-100) 4(-350,100) 5(-250,-100) 6(-250,100) 7(-150,-100) 8(-150,100) 9(-50,-100) 10(-50,100) 11(50,-100) 12(50,100) 13(150,-100) 14(150,100) 15(250,-100) 16(250,100) 17(350,-100) 18(350,100) 19(450,-100) 20(450,100)
  silkscreen extent -505,-135 500,100, body extent -500,-148 500,148, height 382
HDR_2x10-SMD-1.27mm-NC [mm] "SMT MICRO HEADER, (1,27) .050\""
  rect 0.76x2.4 smd: 1(-5.715,-1.95) 2(-5.715,1.95) 3(-4.445,-1.95) 4(-4.445,1.95) 5(-3.175,-1.95) 6(-3.175,1.95) 7(-1.905,-1.95) 8(-1.905,1.95) 9(-0.635,-1.95) 10(-0.635,1.95) 11(0.635,-1.95) 12(0.635,1.95) 13(1.905,-1.95) 14(1.905,1.95) 15(3.175,-1.95) 16(3.175,1.95) 17(4.445,-1.95) 18(4.445,1.95) 19(5.715,-1.95) 20(5.715,1.95)
  silkscreen extent -6.73,-2.38 6.43,1.75
INDC0603X03L_C [mm] "Chip Inductor, 2-Leads, Body 0.6x0.3mm, IPC High Density"
  rect 0.27x0.3 smd: 1(-0.285,0) 2(0.285,0)
  body extent -0.3,-0.15 0.3,0.15, height 0.3
INDC1005X04L [mm] "Chip Inductor, 2-Leads, Body 1.0x0.5mm, IPC High Density"
  rect 0.65x0.5 smd: 1(-0.475,0) 2(0.475,0)
  body extent -0.5,-0.25 0.5,0.25, height 0.5
INDC1608X06L [mm] "Chip Inductor, 2-Leads, Body 1.6x0.8mm, IPC High Density"
  rect 0.75x0.8 smd: 1(-0.675,0) 2(0.675,0)
  silkscreen extent -0.1,-0.3 0.1,0.3, body extent -0.8,-0.4 0.8,0.4, height 0.8
INDC2016X10N [mm] "Chip Inductor, 2-Leads, Body 2.00x1.60mm, IPC Medium Density"
  rect 1.13x1.82 smd: 1(-0.885,0) 2(0.885,0)
  silkscreen extent -1.65,-1.14 1.65,1.14, body extent -1,-0.8 1,0.8, height 1
JS102011JAQN [mm] "Slide Switches - DPDT, SMD, ON-ON"
  round 0.9 hole 0.9 unplated mask+0: 0(-3.4,0) 0(3.4,0)
  rect 0.5x0.5 smd: 1(-2.5,-1.2) 3(2.5,-1.2) 4(-2.5,1.2) 6(2.5,1.2)
  rect 1x1.6 smd: 2(0,-1.2) 5(0,1.2)
  Top Layer region: 3,-0.562 2.838,-0.4 2,-0.4 2,-2 3,-2
  Top Layer region: 3,0.562 2.838,0.4 2,0.4 2,2 3,2
  Top Layer region: -3,-0.562 -2.838,-0.4 -2,-0.4 -2,-2 -3,-2
  Top Layer region: -3,0.562 -2.838,0.4 -2,0.4 -2,2 -3,2
  silkscreen extent -4.5,-3.8 4.5,1.75, body extent -4.25,-3.75 4.25,1.75, height 3.5
LabelSilk_12x12 [mm] "PCA version label, stick-on, 12x12mm"
  silkscreen extent 0,0 12,12, body extent 0,0 12,12, height 0.05
LED_0603_G [mil] "SMD Super Bright LED, GREEN"
  rect 30x32 smd: 1(-27.5,0) 2(27.5,0)
  silkscreen extent -58,-20 48,20, body extent -32,-16 32,16, height 24
LIST_1x2 [mm] "Pin List, 2.54mm through hole"
  rect 1.5x1.5 hole 0.9: 1(-1.27,0)
  round 1.5 hole 0.9: 2(1.27,0)
  body extent -2.54,-1.27 2.44,1.23, height 8.2
LIST_1x3 [mm] "Pin List, 2.54mm through hole"
  rect 1.5x1.5 hole 0.9: 1(-2.54,0)
  round 1.5 hole 0.9: 2(0,0) 3(2.54,0)
  body extent -3.81,-1.27 3.71,1.23, height 8.2
LIST_1x3_SMD [mm] "Pin List, 2.54mm, SMD"
  rect 1.02x2.19 smd: 1(0,1.465) 1(0,-1.465) 2(2.54,-1.465) 2(2.54,1.465) 3(5.08,-1.465) 3(5.08,1.465)
  silkscreen extent -1.27,-1.27 6.35,1.27, body extent -1.27,-2.5 6.35,2.5, height 9.82
NORDIC_LOGO_LYING [mm]
  silkscreen extent -2.57,-2.24 13.7,2.24
Nordic_QFN50P500X500X90-33N [mm] "QFN32 5x5x0.85mm, 0.5mm pitch - Medium Density"
  oval 0.85x0.3 smd: 1(-2.45,1.75) 2(-2.45,1.25) 3(-2.45,0.75) 4(-2.45,0.25) 5(-2.45,-0.25) 6(-2.45,-0.75) 7(-2.45,-1.25) 8(-2.45,-1.75) 17(2.45,-1.75) 18(2.45,-1.25) 19(2.45,-0.75) 20(2.45,-0.25) 21(2.45,0.25) 22(2.45,0.75) 23(2.45,1.25) 24(2.45,1.75)
  oval 0.3x0.85 smd: 9(-1.75,-2.45) 10(-1.25,-2.45) 11(-0.75,-2.45) 12(-0.25,-2.45) 13(0.25,-2.45) 14(0.75,-2.45) 15(1.25,-2.45) 16(1.75,-2.45) 25(1.75,2.45) 26(1.25,2.45) 27(0.75,2.45) 28(0.25,2.45) 29(-0.25,2.45) 30(-0.75,2.45) 31(-1.25,2.45) 32(-1.75,2.45)
  rect 3.5x3.5 smd: 33(0,0)
  silkscreen extent -2.57,-2.57 2.57,2.57, body extent -2.5,-2.5 2.5,2.5, height 0.9
QFN12P40_170X200X55L50X20 [mm] "QFN, 12-Leads, Body 2,1x1,8mm (max), Pitch 0,40mm, IPC Low Density"
  rrect50% 0.72x0.25 smd: 1(-0.64,0.8) 2(-0.64,0.4) 3(-0.64,0) 4(-0.64,-0.4) 5(-0.64,-0.8) 7(0.64,-0.8) 8(0.64,-0.4) 9(0.64,0) 10(0.64,0.4) 11(0.64,0.8)
  rrect50% 0.25x0.72 smd: 6(0,-0.85) 12(0,0.85)
  silkscreen extent -1.47,-1.1 1.01,1.1, body extent -0.85,-1 0.85,1, height 0.55
QFN40P600X600X90-48N [mm] "QFN, 48-Leads, Body 6,0x6,0mm (max), Pitch 0,40mm, IPC Medium Density"
  oval 0.65x0.2 smd mask+0.05: 1(-3.025,2.2) 2(-3.025,1.8) 3(-3.025,1.4) 4(-3.025,1) 5(-3.025,0.6) 6(-3.025,0.2) 7(-3.025,-0.2) 8(-3.025,-0.6) 9(-3.025,-1) 10(-3.025,-1.4) 11(-3.025,-1.8) 12(-3.025,-2.2) 25(3.025,-2.2) 26(3.025,-1.8) 27(3.025,-1.4) 28(3.025,-1) 29(3.025,-0.6) 30(3.025,-0.2) 31(3.025,0.2) 32(3.025,0.6) 33(3.025,1) 34(3.025,1.4) 35(3.025,1.8) 36(3.025,2.2)
  oval 0.2x0.65 smd mask+0.05: 13(-2.2,-3.025) 14(-1.8,-3.025) 15(-1.4,-3.025) 16(-1,-3.025) 17(-0.6,-3.025) 18(-0.2,-3.025) 19(0.2,-3.025) 20(0.6,-3.025) 21(1,-3.025) 22(1.4,-3.025) 23(1.8,-3.025) 24(2.2,-3.025) 37(2.2,3.025) 38(1.8,3.025) 39(1.4,3.025) 40(1,3.025) 41(0.6,3.025) 42(0.2,3.025) 43(-0.2,3.025) 44(-0.6,3.025) 45(-1,3.025) 46(-1.4,3.025) 47(-1.8,3.025) 48(-2.2,3.025)
  rect 4.7x4.7 smd: 49(0,0)
  silkscreen extent -4.02,-3 3,3, body extent -3.02,-3.02 3.02,3.02, height 0.86
RESC0603X03L_C [mm] "Chip Resistor, 2-Leads, Body 0.6x0.3mm, IPC High Density"
  rect 0.27x0.3 smd: 1(-0.285,0) 2(0.285,0)
  body extent -0.3,-0.15 0.3,0.15, height 0.23
RESC1005X04L [mm] "Chip Resistor, 2-Leads, Body 1.0x0.5mm, IPC High Density"
  rect 0.6x0.55 smd mask+0.05: 1(-0.5,0) 2(0.5,0)
  body extent -0.5,-0.25 0.5,0.25, height 0.3
S1751 [mm]
  rect 3.45x1.85 smd: 1(0,0)
  silkscreen extent -2.04,-1.25 2.06,1.25, body extent -1.67,-0.8 1.58,0.85, height 2.05
SD-80259-001 [mm] "USB TYPE C RECEPTACLE, 16 PIN"
  round 0.6 hole 0.6 unplated: 0(-2.89,1.315) 0(2.89,1.315)
  rect 0.6x1.14 smd: A1(-3.2,2.385) A4(-2.4,2.385) A9(2.4,2.385) A12(3.2,2.385)
  rect 0.3x1.14 smd: A5(-1.25,2.385) A6(-0.25,2.385) A7(0.25,2.385) A8(1.25,2.385) B5(1.75,2.385) B6(0.75,2.385) B7(-0.75,2.385) B8(-1.75,2.385)
  oval 0.9x2 hole 0.6 slot 1.7 at 90 deg: SHLD(-4.325,1.795) SHLD(4.325,1.795)
  oval 0.9x1.7 hole 0.6 slot 1.4 at 90 deg: SHLD(-4.325,-2.385) SHLD(4.325,-2.385)
  oval 0.9x2 on Top Paste: ""(-4.32,1.795) ""(4.32,1.795)
  oval 0.9x1.7 on Top Paste: ""(-4.32,-2.385) ""(4.32,-2.385)
  silkscreen extent -4.33,-4.48 4.33,0.47, body extent -4.48,-4.98 4.48,2.74, height 3.26
SEGGER_LOGO_S [mm] "Logo 7.82 mm x 3.84 mm, print overlay"
  silkscreen extent -3.91,-1.92 3.91,1.92
Shunt_2.54mm_Vertical [mm]
  body extent -2.51,-1.24 2.51,1.24, height 9
Solderbridge [mil]
  round 1 smd paste-99999: 1(-13.78,0) 2(13.78,0)
  Top Layer region: 7.49,-19.36 15.76,-15.74 21.55,-8.8 23.62,0 23.62,0 21.55,8.79 15.76,15.74 7.49,19.36 7.49,19.36 6.18,19.31 5.02,18.71 4.22,17.68 3.94,16.4 3.94,16.4 3.94,-16.4 4.22,-17.68 5.02,-18.71 6.18,-19.31 7.49,-19.36
  Top Layer region: -7.49,19.36 -15.76,15.74 -21.55,8.8 -23.62,0 -23.62,0 -21.55,-8.79 -15.76,-15.74 -7.49,-19.36 -7.49,-19.36 -6.18,-19.31 -5.02,-18.71 -4.22,-17.68 -3.94,-16.4 -3.94,-16.4 -3.94,16.4 -4.22,17.68 -5.02,18.71 -6.18,19.31 -7.49,19.36
Solderbridge_0.4#1 [mm]
  round 0.2 smd paste-10: 1(-0.312,0) 2(0.312,0)
  Top Layer region: 0.077,0.553 0.203,0.512 0.335,0.424 0.409,0.351 0.462,0.292 0.521,0.193 0.549,0.099 0.544,-0.122 0.518,-0.193 0.434,-0.33 0.351,-0.411 0.152,-0.536 0.077,-0.559
  Top Layer region: -0.077,-0.553 -0.129,-0.605 -0.205,-0.554 -0.409,-0.351 -0.462,-0.292 -0.521,-0.193 -0.549,-0.099 -0.544,0.122 -0.518,0.193 -0.434,0.33 -0.351,0.411 -0.259,0.469 -0.159,0.556 -0.08,0.565
  Top Layer lines w0.152: -0.156,0.557 ccw(c-0.035,0) -0.312,0.498 ccw(c-0.035,0) -0.45,-0.391 ccw(c-0.035,0) -0.153,-0.558 ; 0.153,0.557 cw(c0.03,0) 0.528,0.279 cw(c0.03,0) 0.153,-0.557
Solderbridge_0.4#2 [mm]
  round 0.2 smd paste-10: 1(-0.312,0) 2(0.312,0)
  Top Layer region: 0.077,0.553 0.203,0.512 0.335,0.424 0.409,0.351 0.462,0.292 0.521,0.193 0.549,0.099 0.544,-0.122 0.518,-0.193 0.434,-0.33 0.351,-0.411 0.152,-0.536 0.077,-0.559
  Top Layer region: -0.077,-0.553 -0.129,-0.605 -0.205,-0.554 -0.409,-0.351 -0.462,-0.292 -0.521,-0.193 -0.549,-0.099 -0.544,0.122 -0.518,0.193 -0.434,0.33 -0.351,0.411 -0.259,0.469 -0.159,0.556 -0.08,0.565
  Top Layer lines w0.152: -0.153,-0.558 cw(c-0.035,0) -0.312,-0.498 cw(c-0.035,0) -0.466,0.373 cw(c-0.035,0) -0.442,0.399 cw(c-0.035,0) -0.408,0.431 cw(c-0.035,0) -0.156,0.557 ; 0.153,-0.557 ccw(c0.03,0) 0.527,-0.279 ccw(c0.03,0) 0.538,-0.259 ccw(c0.03,0) 0.549,-0.237 ccw(c0.03,0) 0.153,0.557
Solderbridge_Shorted [mil]
  round 1 smd paste-99999: 1(-13.78,0) 2(13.78,0)
  Top Layer region: -4.92,3.94 -4.92,-3.94 4.92,-3.94 4.92,3.94
  Top Layer region: -7.49,19.36 -15.76,15.74 -21.55,8.8 -23.62,0 -23.62,0 -21.55,-8.79 -15.76,-15.74 -7.49,-19.36 -7.49,-19.36 -6.18,-19.31 -5.02,-18.71 -4.22,-17.68 -3.94,-16.4 -3.94,-16.4 -3.94,16.4 -4.22,17.68 -5.02,18.71 -6.18,19.31 -7.49,19.36
  Top Layer region: 7.49,-19.36 15.76,-15.74 21.55,-8.8 23.62,0 23.62,0 21.55,8.79 15.76,15.74 7.49,19.36 7.49,19.36 6.18,19.31 5.02,18.71 4.22,17.68 3.94,16.4 3.94,16.4 3.94,-16.4 4.22,-17.68 5.02,-18.71 6.18,-19.31 7.49,-19.36
Solderbridge_SHORTED_0.4 [mm]
  round 0.2 smd paste-10: 1(-0.312,0) 2(0.312,0)
  Top Layer region: -0.077,-0.553 -0.129,-0.605 -0.205,-0.554 -0.409,-0.351 -0.462,-0.292 -0.521,-0.193 -0.549,-0.099 -0.544,0.122 -0.518,0.193 -0.434,0.33 -0.351,0.411 -0.259,0.469 -0.159,0.556 -0.08,0.565
  Top Layer region: 0.077,0.553 0.203,0.512 0.335,0.424 0.409,0.351 0.462,0.292 0.521,0.193 0.549,0.099 0.544,-0.122 0.518,-0.193 0.434,-0.33 0.351,-0.411 0.152,-0.536 0.077,-0.559
  Top Layer lines w0.152: 0.153,0.557 cw(c0.03,0) 0.153,-0.557 ; -0.153,-0.558 cw(c-0.035,0) -0.156,0.557
  Top Layer lines w0.203: 0.363,0 -0.312,0
SON127P600X80_HS-9N [mm] "SON, 8-Leads, Body 5.00x6.00mm, Pitch 1.27mm, Thermal Pad 4.00x3.40mm, IPC Medium Density"
  rect 1.15x0.45 smd: 1(-2.77,1.905) 2(-2.77,0.635) 3(-2.77,-0.635) 4(-2.77,-1.905) 5(2.77,-1.905) 6(2.77,-0.635) 7(2.77,0.635) 8(2.77,1.905)
  rect 3.4x4 smd paste-1.7: 9(0,0)
  silkscreen extent -3.98,-2.6 3.1,2.67, body extent -3.05,-2.55 3.05,2.55, height 0.8
SOT95P280X145-5N [mm] "SOT23, 5-Leads, Body 2,90x2,80mm, Pitch 0,95mm, IPC Medium Density"
  rect 1x0.6 smd: 1(-1.35,0.95) 2(-1.35,0) 3(-1.35,-0.95) 4(1.35,-0.95) 5(1.35,0.95)
  silkscreen extent -1.47,-1.5 0.45,1.92, body extent -1.5,-1.55 1.5,1.55, height 1.45
Switch-PB-6.2x6.3mm-SMD [mm] "6.2×6.5mm TACT Switch, without ground connector"
  rect 2.75x1.4 smd: 1(-3.375,2) 1(3.375,2) 2(-3.375,-2) 2(3.375,-2)
  silkscreen extent -3,-3 3,3, body extent -3.6,-3.1 3.6,3.1, height 2.5
TC2050-IDC-NLFP [mil]
  round 39 hole 39 unplated mask+0.79: 0(-150,0) 0(150,-40) 0(150,40)
  round 31 smd paste-196.85: 1(-100,-25) 2(-50,-25) 3(0,-25) 4(50,-25) 5(100,-25) 6(100,25) 7(50,25) 8(0,25) 9(-50,25) 10(-100,25)
  Top Layer pour cut-out: -100,25 -100,-25 100,-25 100,25
TP_SMD_D0.7mm [mm] "Test point - pad 0.7mm"
  round 0.7 smd paste-5: 1(0,0)
  silkscreen extent -0.63,-0.64 0.63,0.63
TP_SMD_D1.5mm#1 [mm] "Test point - pad 1.5mm"
  round 1.5 smd paste-5: 1(0,0)
  body extent -0.75,-0.75 0.75,0.75, height 0.05
TP_SMD_D1.5mm#2 [mm] "Test point - pad 1.5mm"
  round 1.5 smd paste-5: 1(0,0.01)
  body extent -0.75,-0.75 0.75,0.75, height 0.05
TSSOP6 [mm] "TSSOP6 (SOT-363)"
  rect 0.6x0.6 smd: 1(-0.75,-0.9) 3(0.75,-0.9) 4(0.75,0.9) 6(-0.75,0.9)
  rect 0.4x0.6 smd: 2(0,-0.9) 5(0,0.9)
  silkscreen extent -1.47,-1.07 1,0.45, body extent -1,-1.05 1,1.05, height 0.93
UFDFN50P120X250X55-8N [mm]
  round 0.025 smd: 1(-0.5,0.75) 4(-0.5,-0.75) 5(0.5,-0.75) 8(0.5,0.75)
  rect 0.6x0.2 smd: 2(-0.5,0.25) 3(-0.5,-0.25) 6(0.5,-0.25) 7(0.5,0.25)
  Top Layer region: -0.2,0.65 -0.8,0.65 -0.8,0.85 -0.4,0.85 -0.4,1.05 -0.2,1.05
  Top Layer region: 0.4,0.85 0.8,0.85 0.8,0.65 0.2,0.65 0.2,1.05 0.4,1.05
  Top Layer region: -0.2,-1.05 -0.4,-1.05 -0.4,-0.85 -0.8,-0.85 -0.8,-0.65 -0.2,-0.65
  Top Layer region: 0.8,-0.85 0.4,-0.85 0.4,-1.05 0.2,-1.05 0.2,-0.65 0.8,-0.65
  silkscreen extent -1.08,-1.37 0.6,1.37, body extent -0.6,-1.25 0.6,1.25, height 0.6
WEE_3x4.5mm [mm]
  silkscreen extent -1.47,-2.7 1.47,1.71
XQFN40P180X260X50-16N#1 [mm] "QFN, 16-Leads, Body 1.80x2.60mm, Pitch 0.40mm, IPC Medium Density"
  rect 0.65x0.22 smd paste-0.02 mask+0.035: 1(-0.725,0.6)
  rect 0.55x0.22 smd paste-0.02 mask+0.035: 2(-0.775,0.2) 3(-0.775,-0.2) 4(-0.775,-0.6) 9(0.775,-0.6) 10(0.775,-0.2) 11(0.775,0.2) 12(0.775,0.6)
  rect 0.22x0.55 smd paste-0.02 mask+0.035: 5(-0.6,-1.175) 6(-0.2,-1.175) 7(0.2,-1.175) 8(0.6,-1.175) 13(0.6,1.175) 14(0.2,1.175) 15(-0.2,1.175) 16(-0.6,1.175)
  silkscreen extent -1.36,-1.37 0.97,1.37, body extent -0.9,-1.3 0.9,1.3, height 0.55
XQFN40P180X260X50-16N#2 [mm] "QFN, 16-Leads, Body 1.80x2.60mm, Pitch 0.40mm, IPC Medium Density"
  rect 0.65x0.22 smd paste-0.02 mask+0.05: 1(-0.725,0.6)
  rect 0.55x0.22 smd paste-0.02 mask+0.03: 2(-0.775,0.2) 3(-0.775,-0.2) 4(-0.775,-0.6) 9(0.775,-0.6) 10(0.775,-0.2) 11(0.775,0.2) 12(0.775,0.6)
  rect 0.22x0.55 smd paste-0.02 mask+0.03: 5(-0.6,-1.175) 6(-0.2,-1.175) 7(0.2,-1.175) 8(0.6,-1.175) 13(0.6,1.175) 14(0.2,1.175) 15(-0.2,1.175) 16(-0.6,1.175)
  silkscreen extent -1.36,-1.37 0.97,1.37, body extent -0.9,-1.3 0.9,1.3, height 0.55
XTAL_2012 [mm] "XTAL SMD 2.0 x 1.2 mm"
  rect 0.75x1.4 smd: 1(-0.725,0) 2(0.725,0)
  silkscreen extent -0.17,-0.6 0.17,0.6, body extent -1,-0.61 1,0.61, height 0.6

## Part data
C1 C2: library part C0201-2µ2-2.5V-X6T-GRM033D80E225ME47D, "Capacitor, Ceramic, 2.2µF 2.5V X6T 0201,±20%", Manufacturer=Murata, Manufacturer Part Number=GRM033R61A225KE47, Part number IPS=N.A., Part number NEMS=100200527, Supplier Part Number 1=81-GRM033D80E225ME7D
C3: library part C0402-10µF-6.3V-X6S, "Capacitor, X6S, ±20%, 6.3V", Manufacturer=N.A., Part number NEMS=100200478
C4 C7 C8 C10 C11 C13 C14 C15 C18 C20 C21 C22 C25 C29 C34 C35 C36 C37 C44 C46 C48 C49 C52 C53 C55 C56 C57 C62 C63 C64 C65 C66 C69 C70 C72 C73 C74 C75 C76 C77 C78 C79: library part C0201-100n, "Capacitor, X5R, ±10%", Manufacturer=N.A., Part number IPS="00000001248, 00000002505", Part number NEMS=100200078, Part number Norautron=262071862
C5 C33: library part C0201-2n2, "Capacitor, X7R, ±10%, 10V", Manufacturer=N.A., Part number IPS=00000001778, Part number NEMS=100200060, Part number Norautron=26470002
C6: library part C0201-1.5p-25V-NP0-GJM0335C1E1R5WB01, "Capacitor, NP0, ±0.05pF, 25V, High Q", Manufacturer=Murata, Manufacturer Part Number=GJM0335C1E1R5WB01, Part number IPS=N.A., Part number NEMS=100200477, Supplier Part Number 1=490-11176-2-ND
C9: library part C0201-2.0p-HQ-Murata, "Capacitor, NP0, ±0.05pF, 25V", Manufacturer=Murata, Manufacturer Part Number=GJM0335C1E2R0WB01, Part number IPS=00000001775, Part number NEMS=100200419, Part number Norautron=N.A.
C12 C30 C67: library part C0201-10n, "Capacitor, X7R, ±10%", Manufacturer=N.A., Part number IPS=00000003480, Part number NEMS=100200067, Part number Norautron=26621779
C16 C28 C31 C32 C39 C45 C50 C51 C68: library part C0402-1µ0-6.3V-X5R-10%, "Capacitor, X5R, ±10%, 6.3V", Manufacturer=N.A., Part number NEMS=100200498, Part number Norautron=26207137
C17 C19: library part C0402-300p, "Capacitor, C0G, ±5%, 50V", Manufacturer=N.A., Part number IPS=00000007788, Part number NEMS=100200155, Supplier Part Number 1=490-3234-1-ND
C23: library part C0402-2µ2-10V, "Capacitor, X5R, ±10%", Manufacturer=N.A., Part number NEMS=100200376, Supplier Part Number 1=490-10451-1-ND
C24 C26 C27: library part C0603-10µ-10V-X7T-GRM188D71A106MA73, "Capacitor, X7T, ±20%, 10V", Manufacturer=Murata, Manufacturer Part Number=GRM188D71A106MA73, Part number IPS=00000004696, Part number NEMS=100200414, Part number Norautron=N.A., Supplier Part Number 1=490-7200-1-ND
C38: library part C0201-1.4p-25V-GJM0335C1E1R4WB01D, "Capacitor, C0G, ±0.05pF, 25V", Manufacturer=Murata, Manufacturer Part Number=GJM0335C1E1R4WB01D, Part number IPS=N.A., Part number NEMS=100200553, Supplier Part Number 1=490-GJM0335C1E1R4WB01DTR-ND
C40: library part C0603-2µ2-6.3V-X7R, "Capacitor, X7R, ±10%, 6.3V", Manufacturer=N.A., Part number NEMS=100200272
C41: library part C0402-100n, "Capacitor, X7R, ±10%", Manufacturer=N.A., Part number IPS=00000005296, Part number NEMS=100200184
C42 C43 C54 C58: library part C0603-4µ7-10V-X7S, "Capacitor, X7S, ±10%, 10V", Manufacturer=N.A., Part number IPS=00000001779, Part number NEMS=100200351, Supplier Part Number 1=445-14258-1-ND
C47: library part C0402-1µ0-16V-X5R, "Capacitor, Ceramic, X5R, ±10%, 16V", Manufacturer=Murata, Manufacturer Part Number=GRT155R61C105KE01D, Part number IPS=N.A., Part number NEMS=100200452, Supplier Part Number 1=490-12255-1-ND
C59: library part C0603-10n-100V-X7R, "Capacitor, X7R, ±10%, 100V", Manufacturer=Murata, Manufacturer Part Number=GCM188R72A103KA37D, Part number IPS=N.A., Part number NEMS=100200349, Supplier Part Number 1=490-4781-1-ND
C60: library part C0201-3.9p-HQ-Murata, "Capacitor, NP0, ±0.05pF, 25V", Manufacturer=Murata, Manufacturer Part Number=GJM0333C1E3R9WB01, Part number IPS=N.A., Part number NEMS=100200424
C61: library part C0201-0.3p-50V-GRM0335C1HR30BA01, "Capacitor, C0G, ±0.1pF, 50V", Manufacturer=Murata, Manufacturer Part Number=GRM0335C1HR30BA01, Part number IPS=N.A., Part number NEMS=100200650, Supplier Part Number 1=490-6135-2-ND
FB1: library part FB0201-120R@100M-200mA-BLM03AG121SN1D, "Ferrite Bead, 120 Ohm @ 100MHz, 200mA, 500 mOhm Max", Manufacturer=Murata, Manufacturer Part Number=BLM03AG121SN1D, Part number IPS=N.A., Part number NEMS=100300419, Supplier Part Number 1=490-5622-1-ND
FB2 FB3: library part FB0402-120R@100M-500mA, "Ferrite Bead, 120 Ohm @ 100MHz, 500mA, 250 mOhm Max", Manufacturer=Murata, Manufacturer Part Number=BLM15AG121SN1D, Part number IPS=00000009954, Part number NEMS=100300099, Part number Norautron=265230631, Supplier Part Number 1=490-1005-1-ND
Fid1 Fid2 Fid3: library part Fid-Mark, "Fiducial Mark", Manufacturer=N.A., Part number NEMS=100500073
J1: "Coaxial Connector with Switch", Manufacturer=Murata, Part number IPS=00000009955, Part number NEMS=100500400, Part number Norautron=26030338, Supplier Part Number 1=490-4981-1-ND
J3: library part SD-80259-1021, "USB-C Receptacle, 16 Pin, USB 2.0", Manufacturer="Bellweather Electronic Corp.", Part number IPS=N.A., Part number NEMS=100500830
J4: library part TC2050-IDC-NLFP, "CBL PLUG-OF-NAILS 10-PIN", Manufacturer="Tag-Connect LLC", Part number IPS=N.A., Part number NEMS=100500463, Supplier Part Number 1=TC2050-IDC-NL-ND
J7: library part FPC_05P-0.5mm-RA-SMD, "0.5mm FPC, 5P,Right Angle SMT,Double Contact,H=1.2mm,White, Tin plated", Manufacturer=WCON, Manufacturer Part Number=5141-05RZDNWR03, Part number IPS=N.A., Part number NEMS=100500528
JP1: library part "SHUNT JUMPER 2.54mm Black Vertical", "Shunt Jumper 2.54mm Black, open top", Manufacturer=WCON, Manufacturer Part Number=3710-6001OS0B05, Part number IPS=N.A., Part number NEMS=100500728
L1: library part L0603-4µ7-MLZ1608M4R7WT000, "Inductor, 120mA, ±20%, 0.65R", Manufacturer="TDK Corporation", Manufacturer Part Number=MLZ1608M4R7WT000, Part number IPS=N.A., Part number NEMS=100300440, Supplier Part Number 1=445-6390-2-ND
L2: library part L0201-2n7-HQ-Murata, "Inductor, 600mA, ±0.1ｎH, 120mOhm", Manufacturer=Murata, Manufacturer Part Number=LQP03HQ2N7B02, Part number IPS=00000001753, Part number NEMS=100300214, Part number Norautron=N.A., Supplier Part Number 1=490-13909-1-ND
